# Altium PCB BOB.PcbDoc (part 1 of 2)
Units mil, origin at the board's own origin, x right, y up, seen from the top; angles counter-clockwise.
Board outline 7000 x 12000 mil, 6 copper layers (Top Layer, Int1 (GND), Int2 (Sign), Int3 (Sign), Int4 (GND2), Bottom Layer), stack 63.868 mil thick; 173 components, 165 nets, 617 pads, 174 vias.
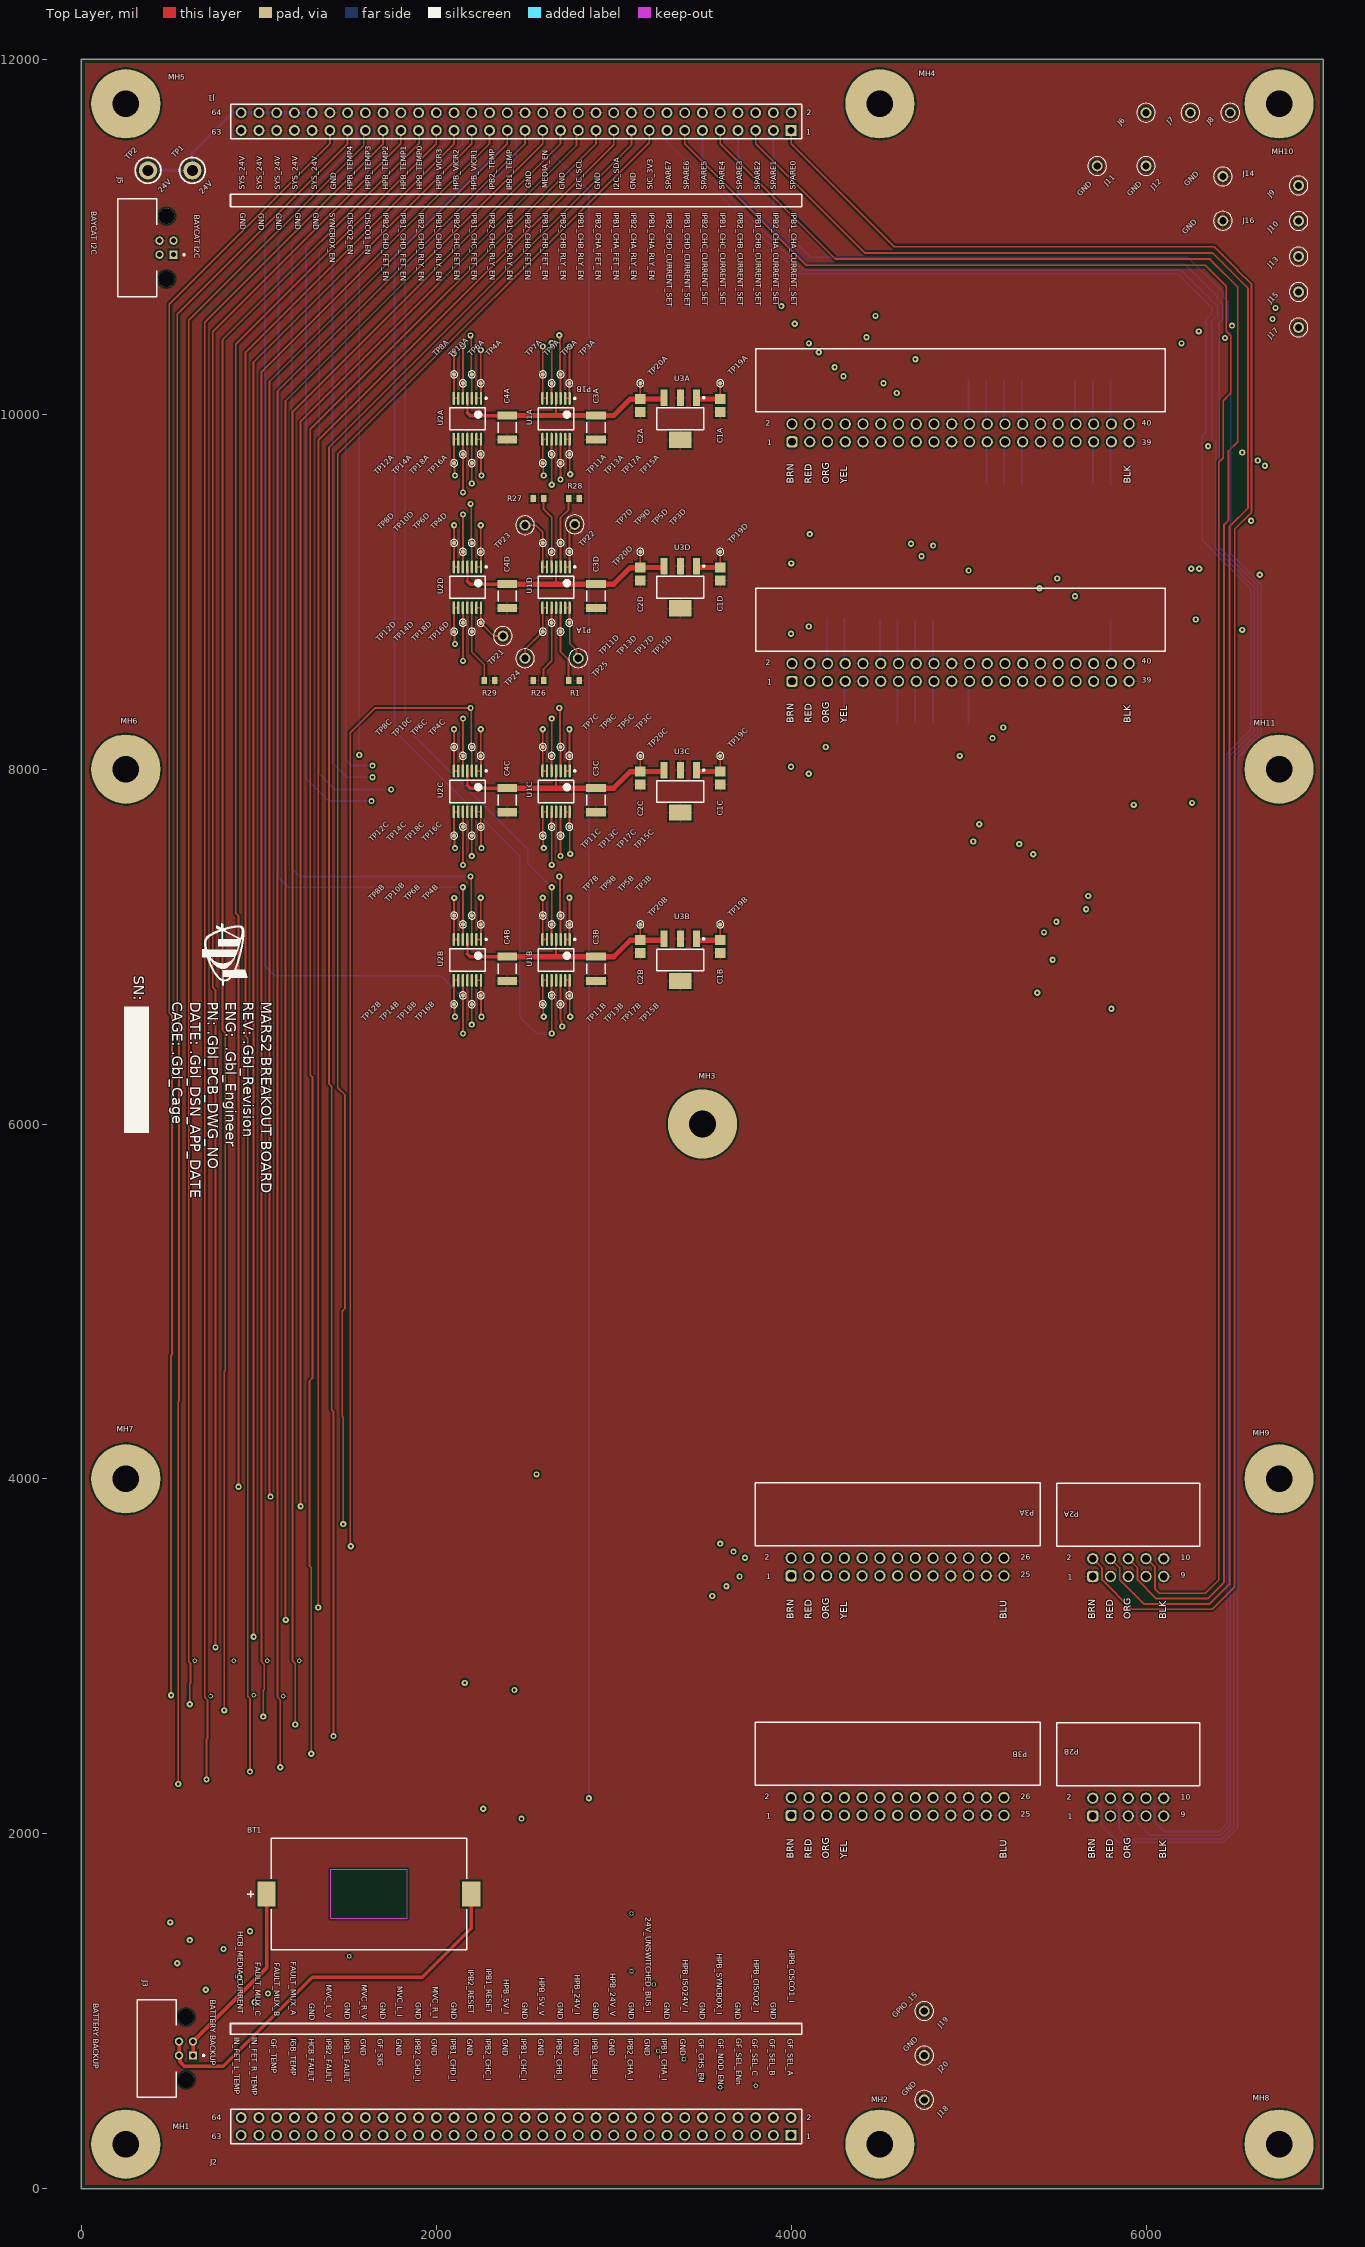
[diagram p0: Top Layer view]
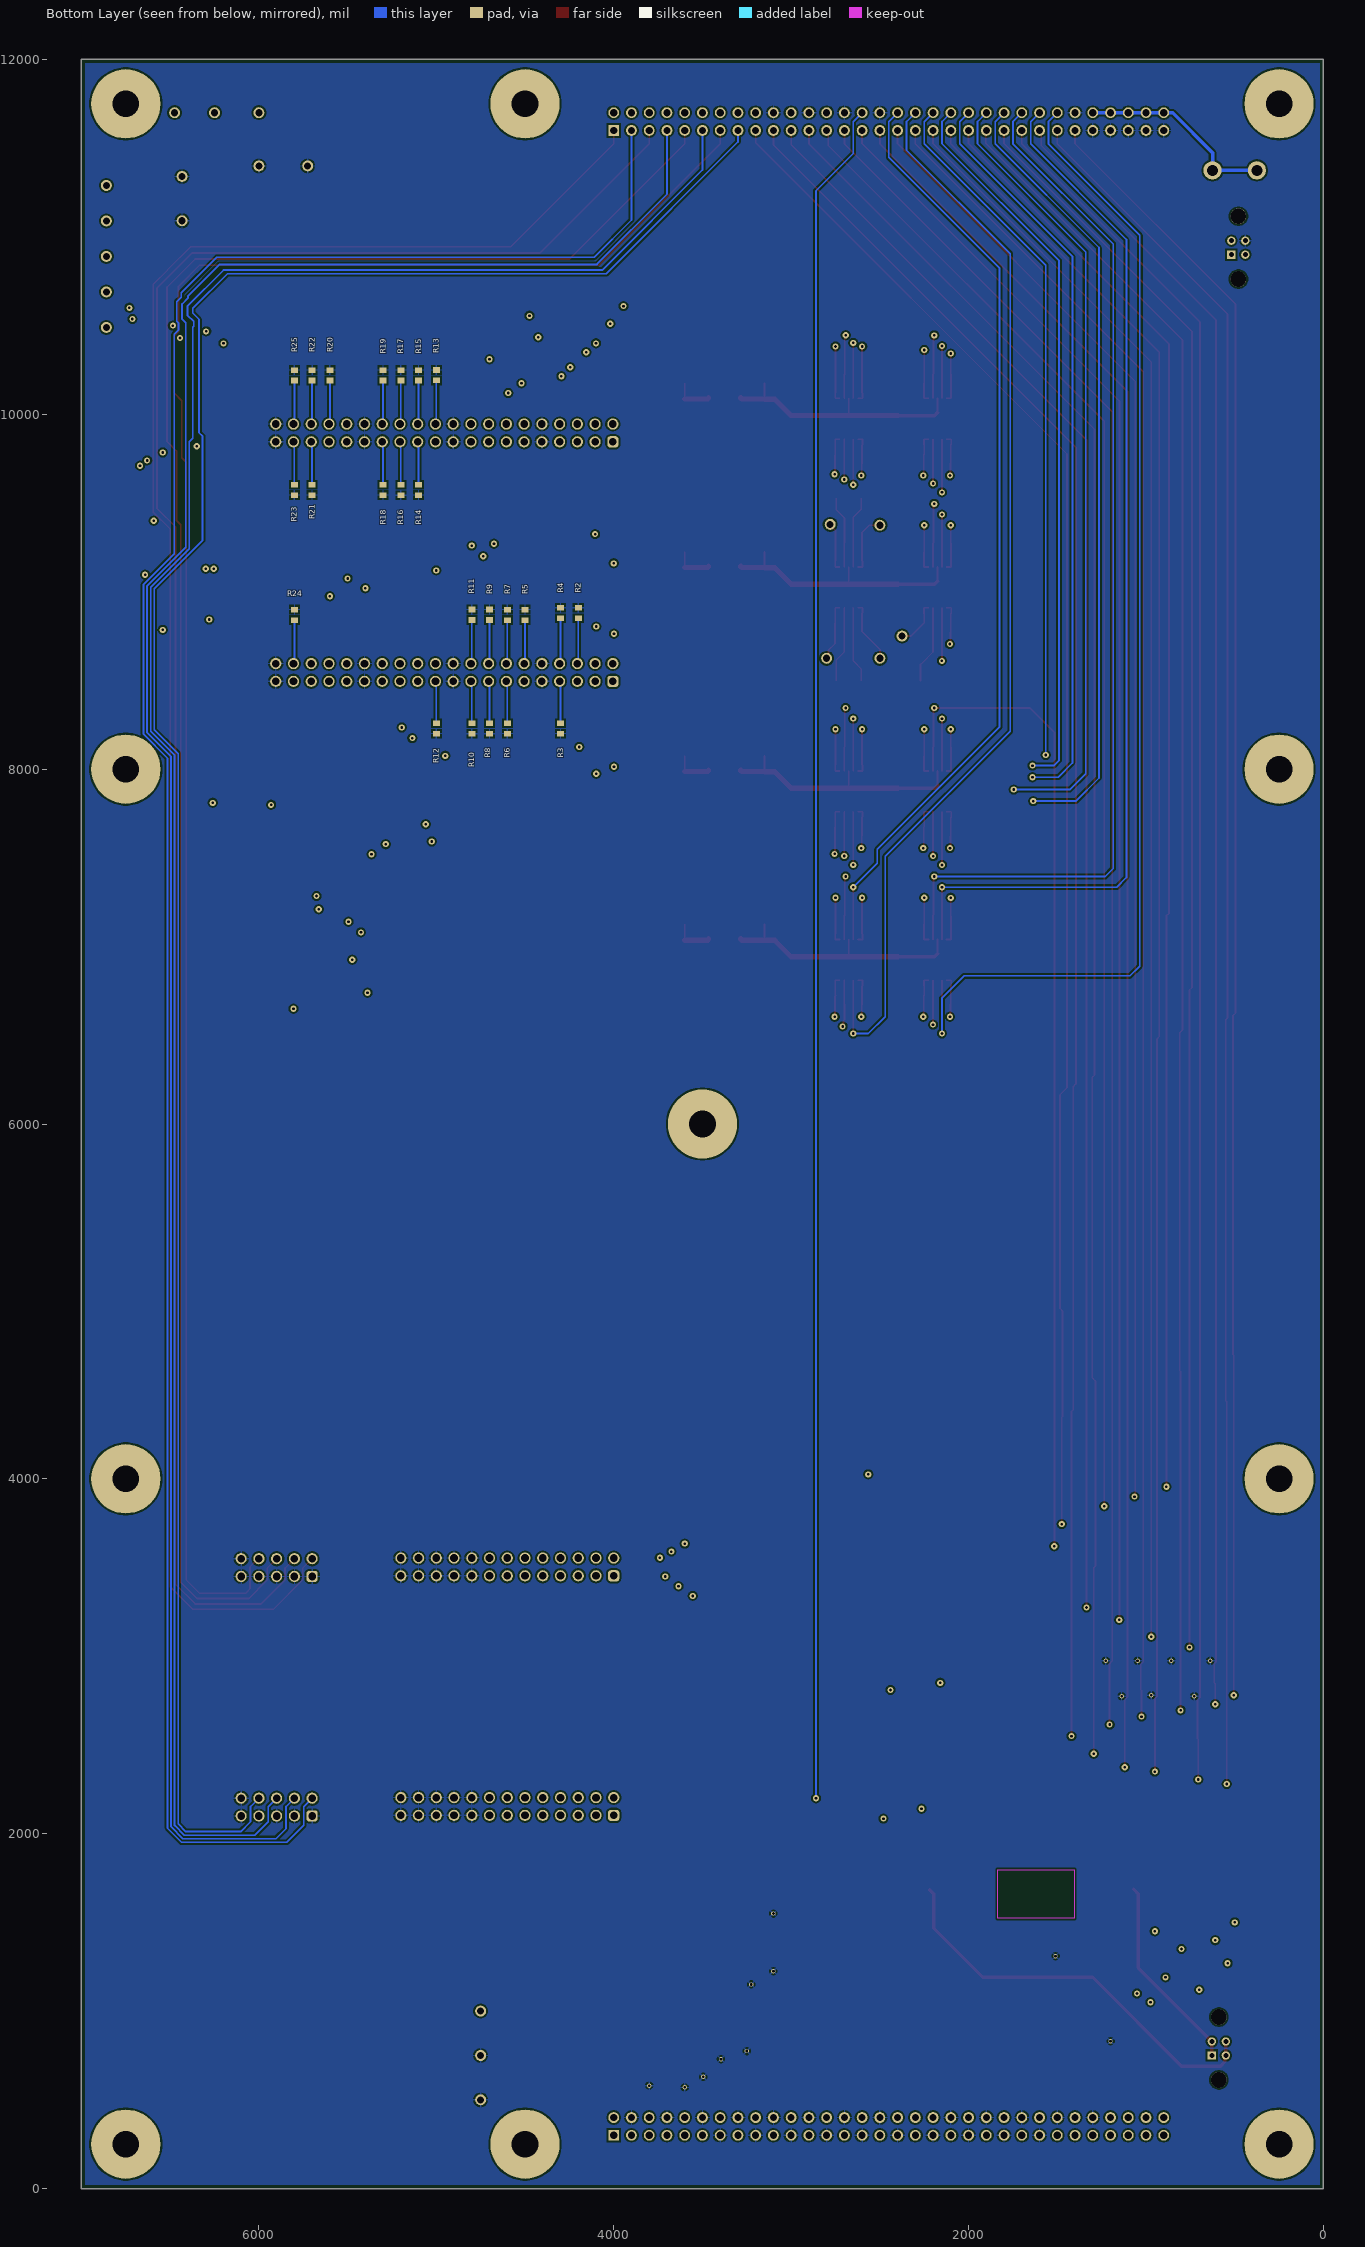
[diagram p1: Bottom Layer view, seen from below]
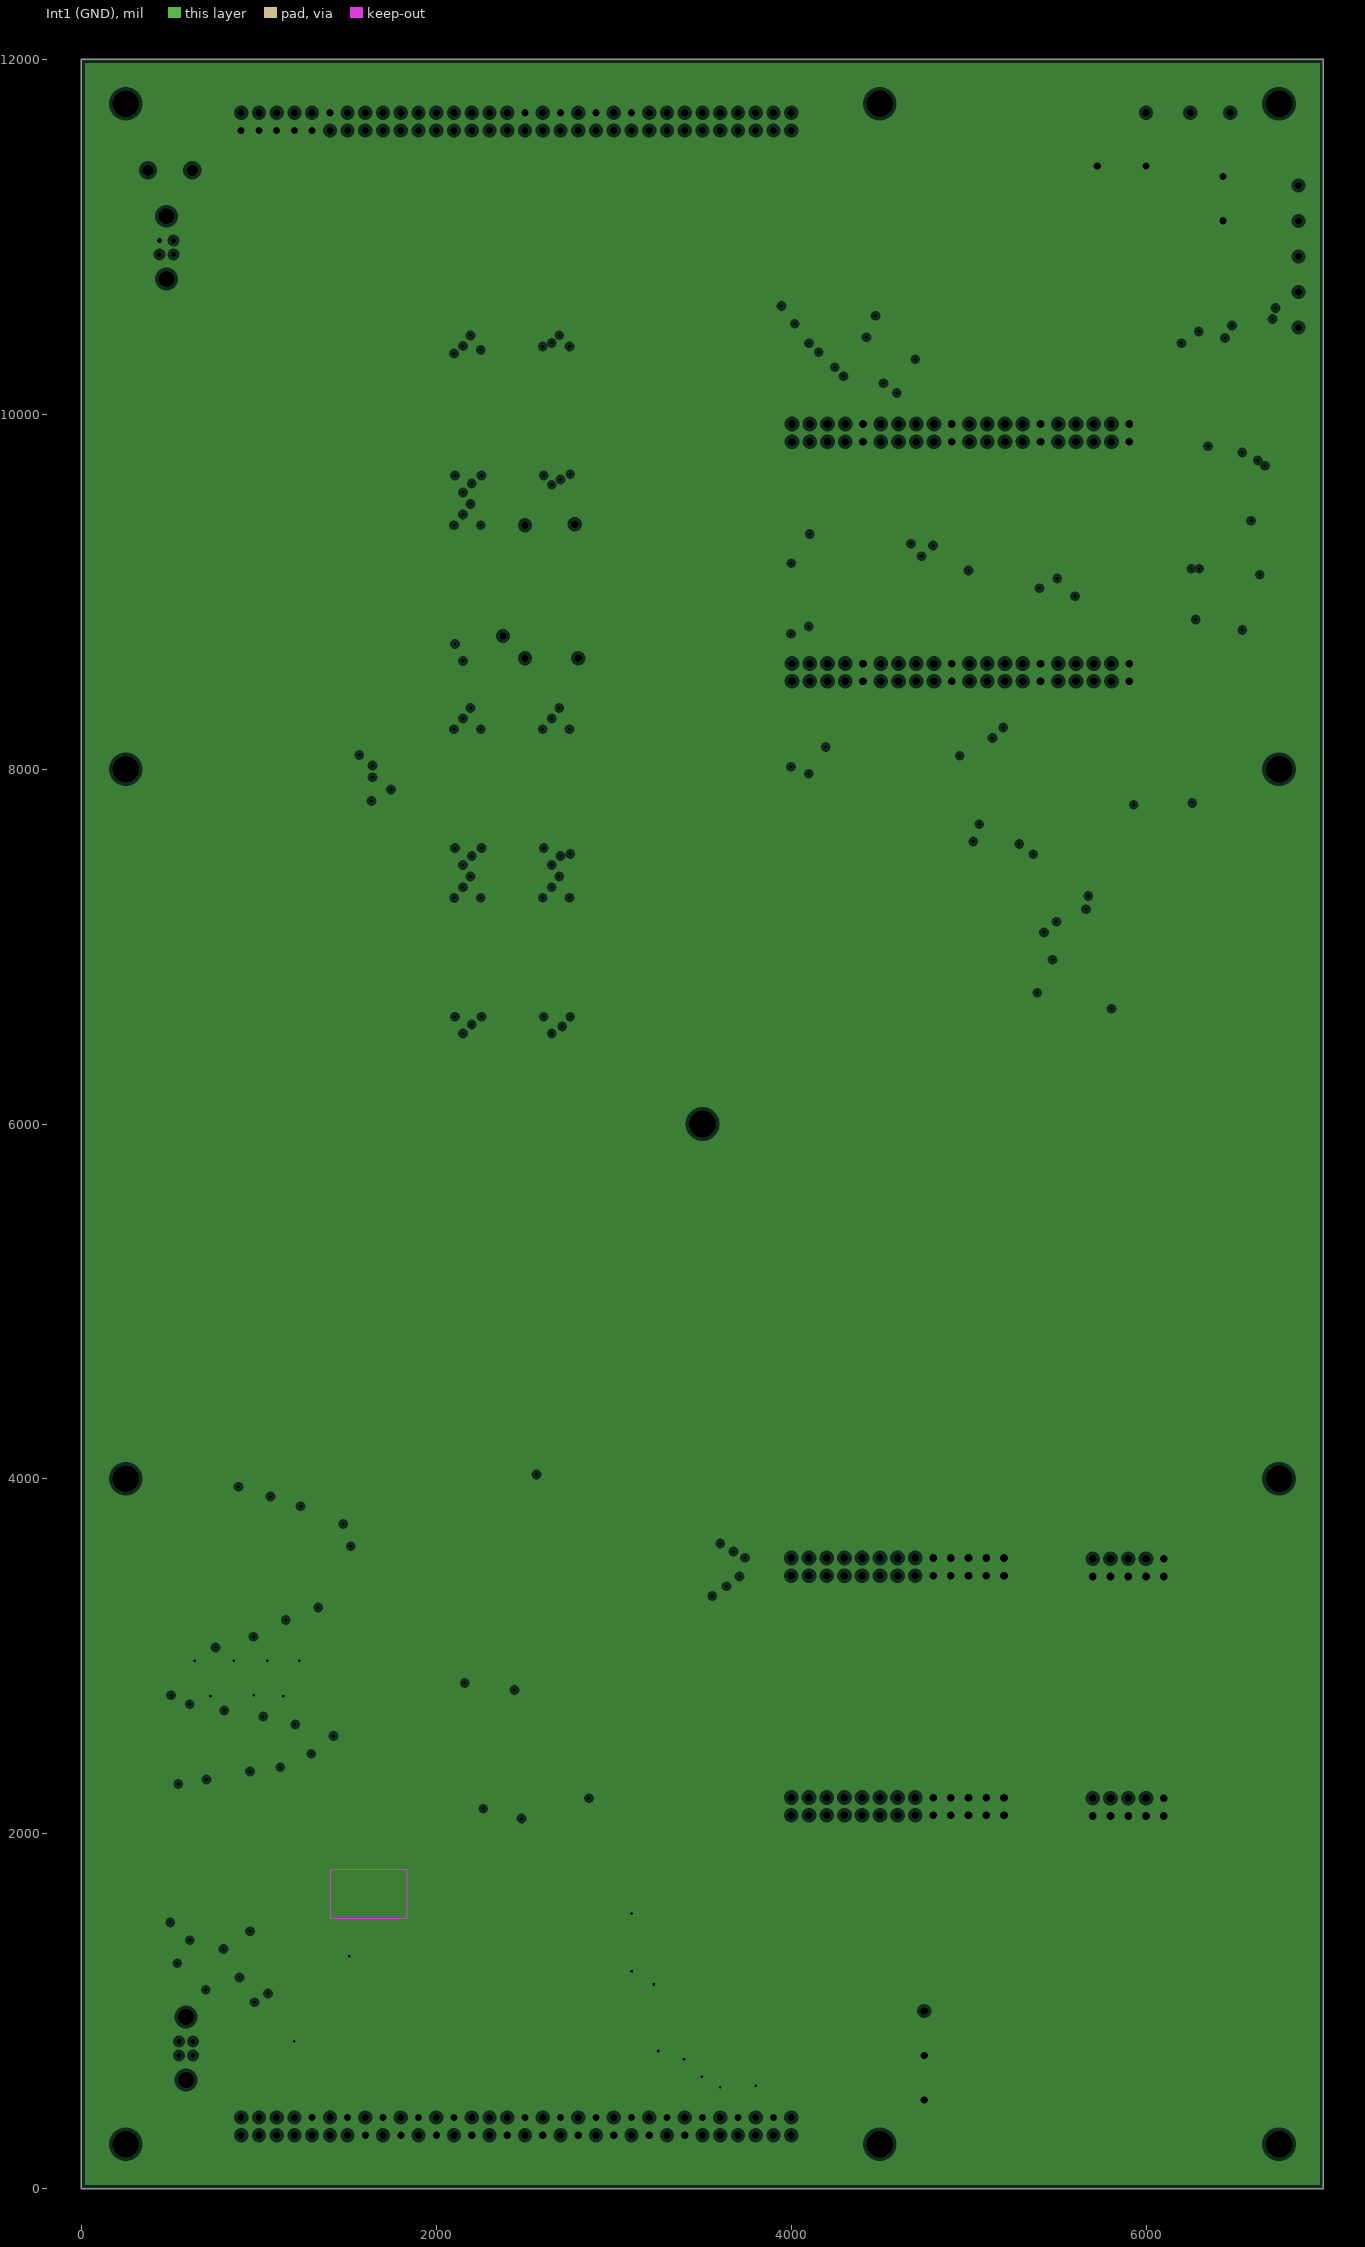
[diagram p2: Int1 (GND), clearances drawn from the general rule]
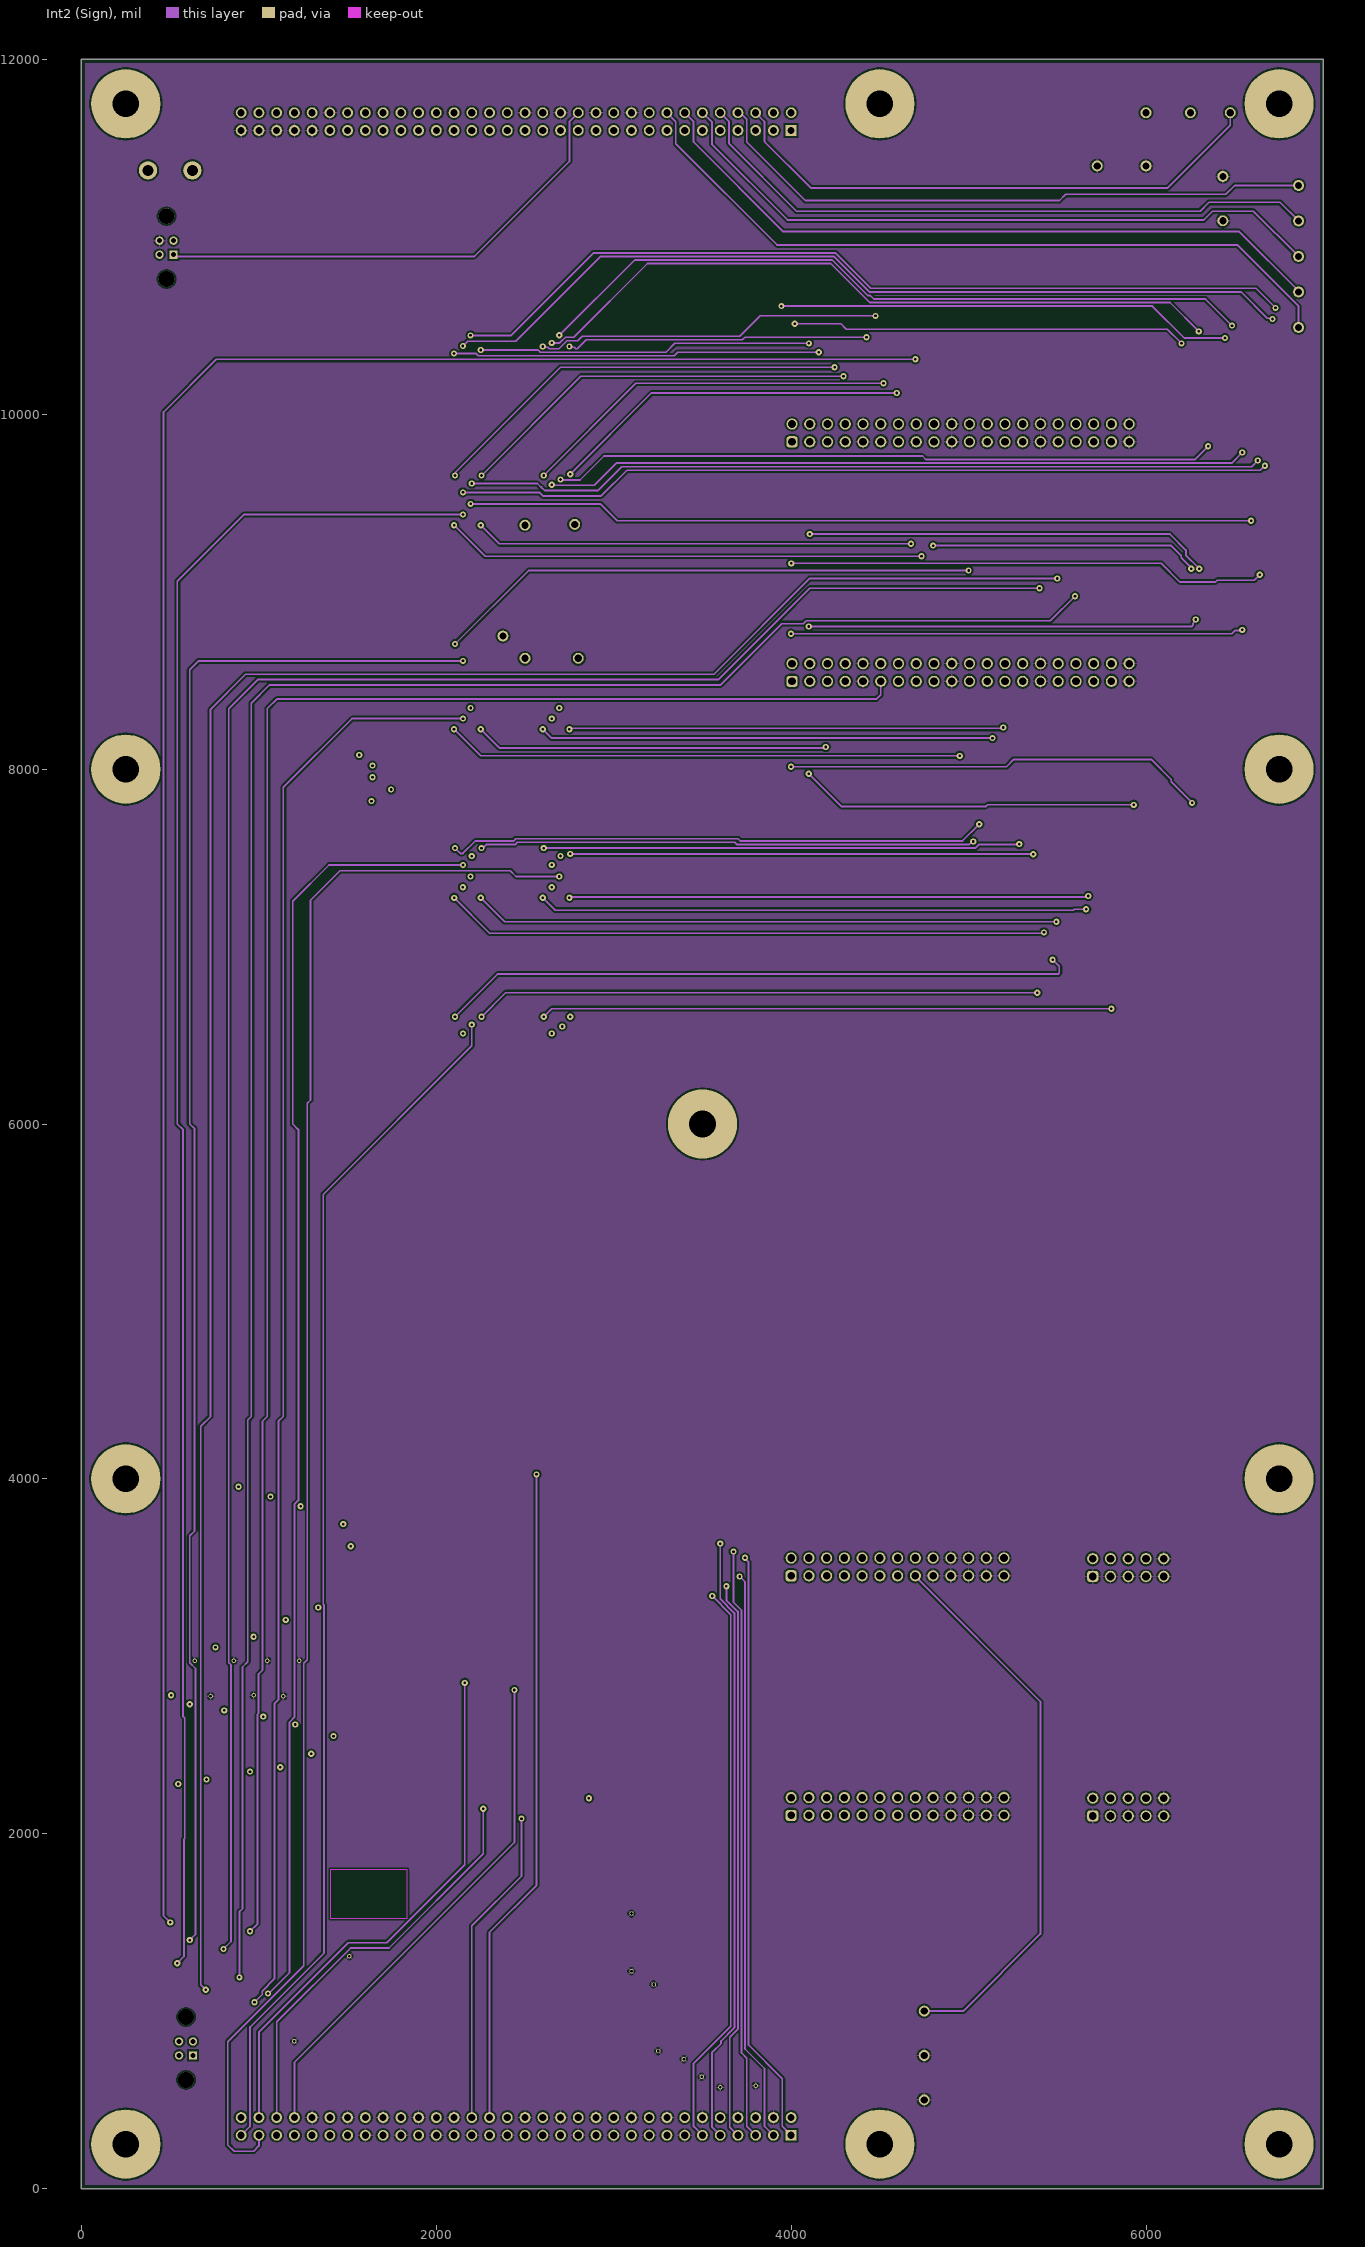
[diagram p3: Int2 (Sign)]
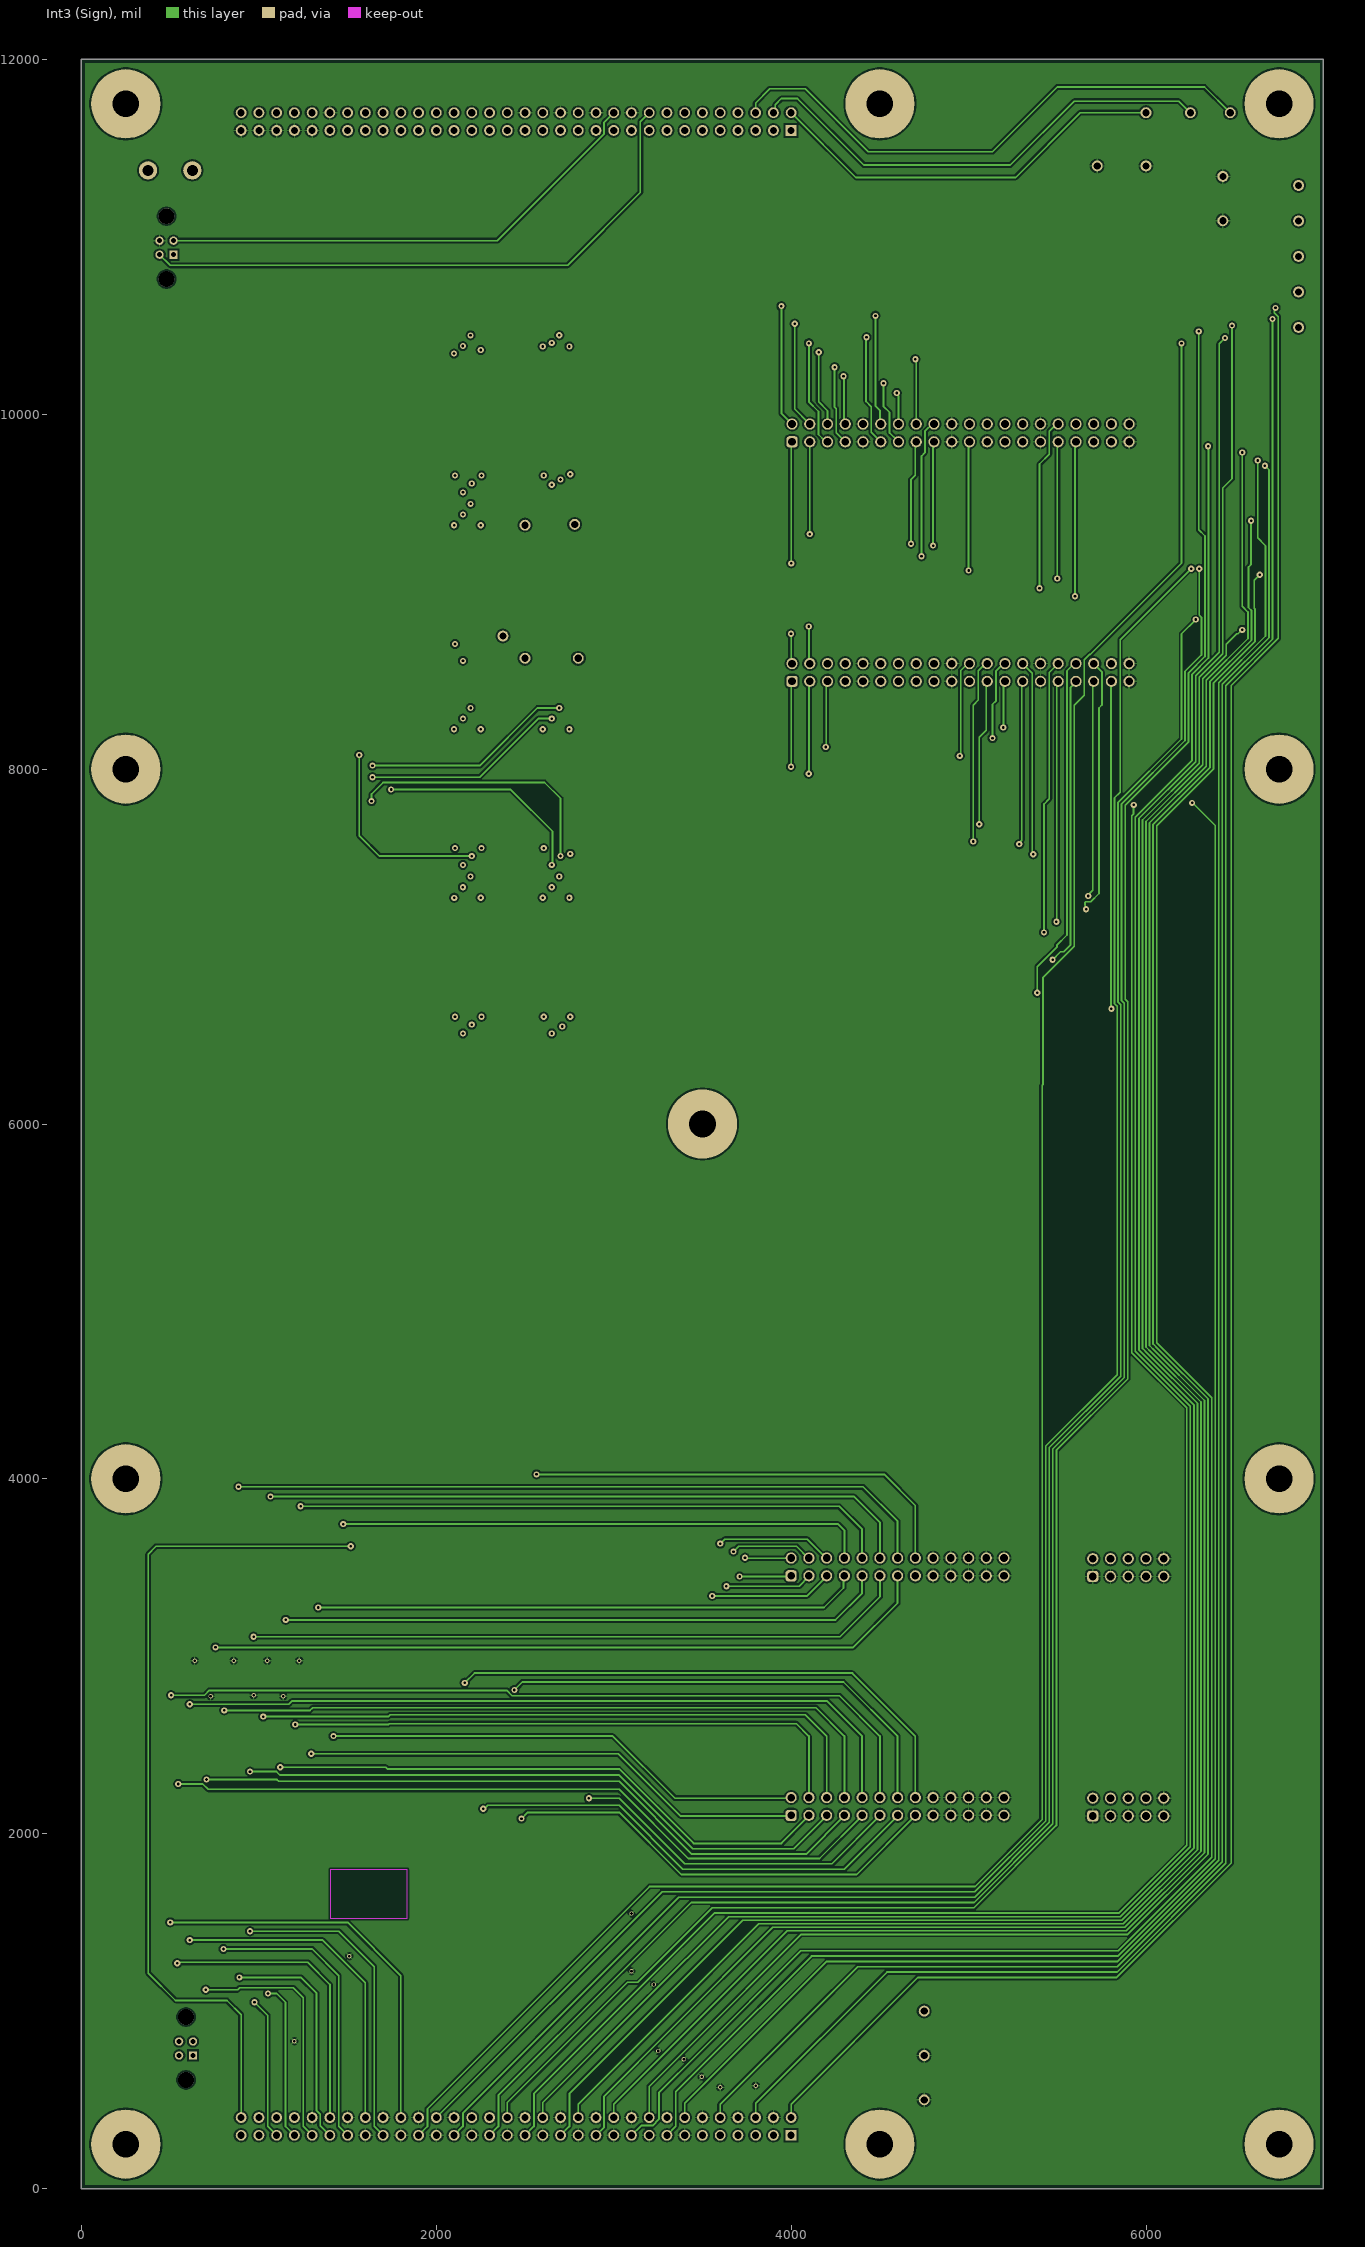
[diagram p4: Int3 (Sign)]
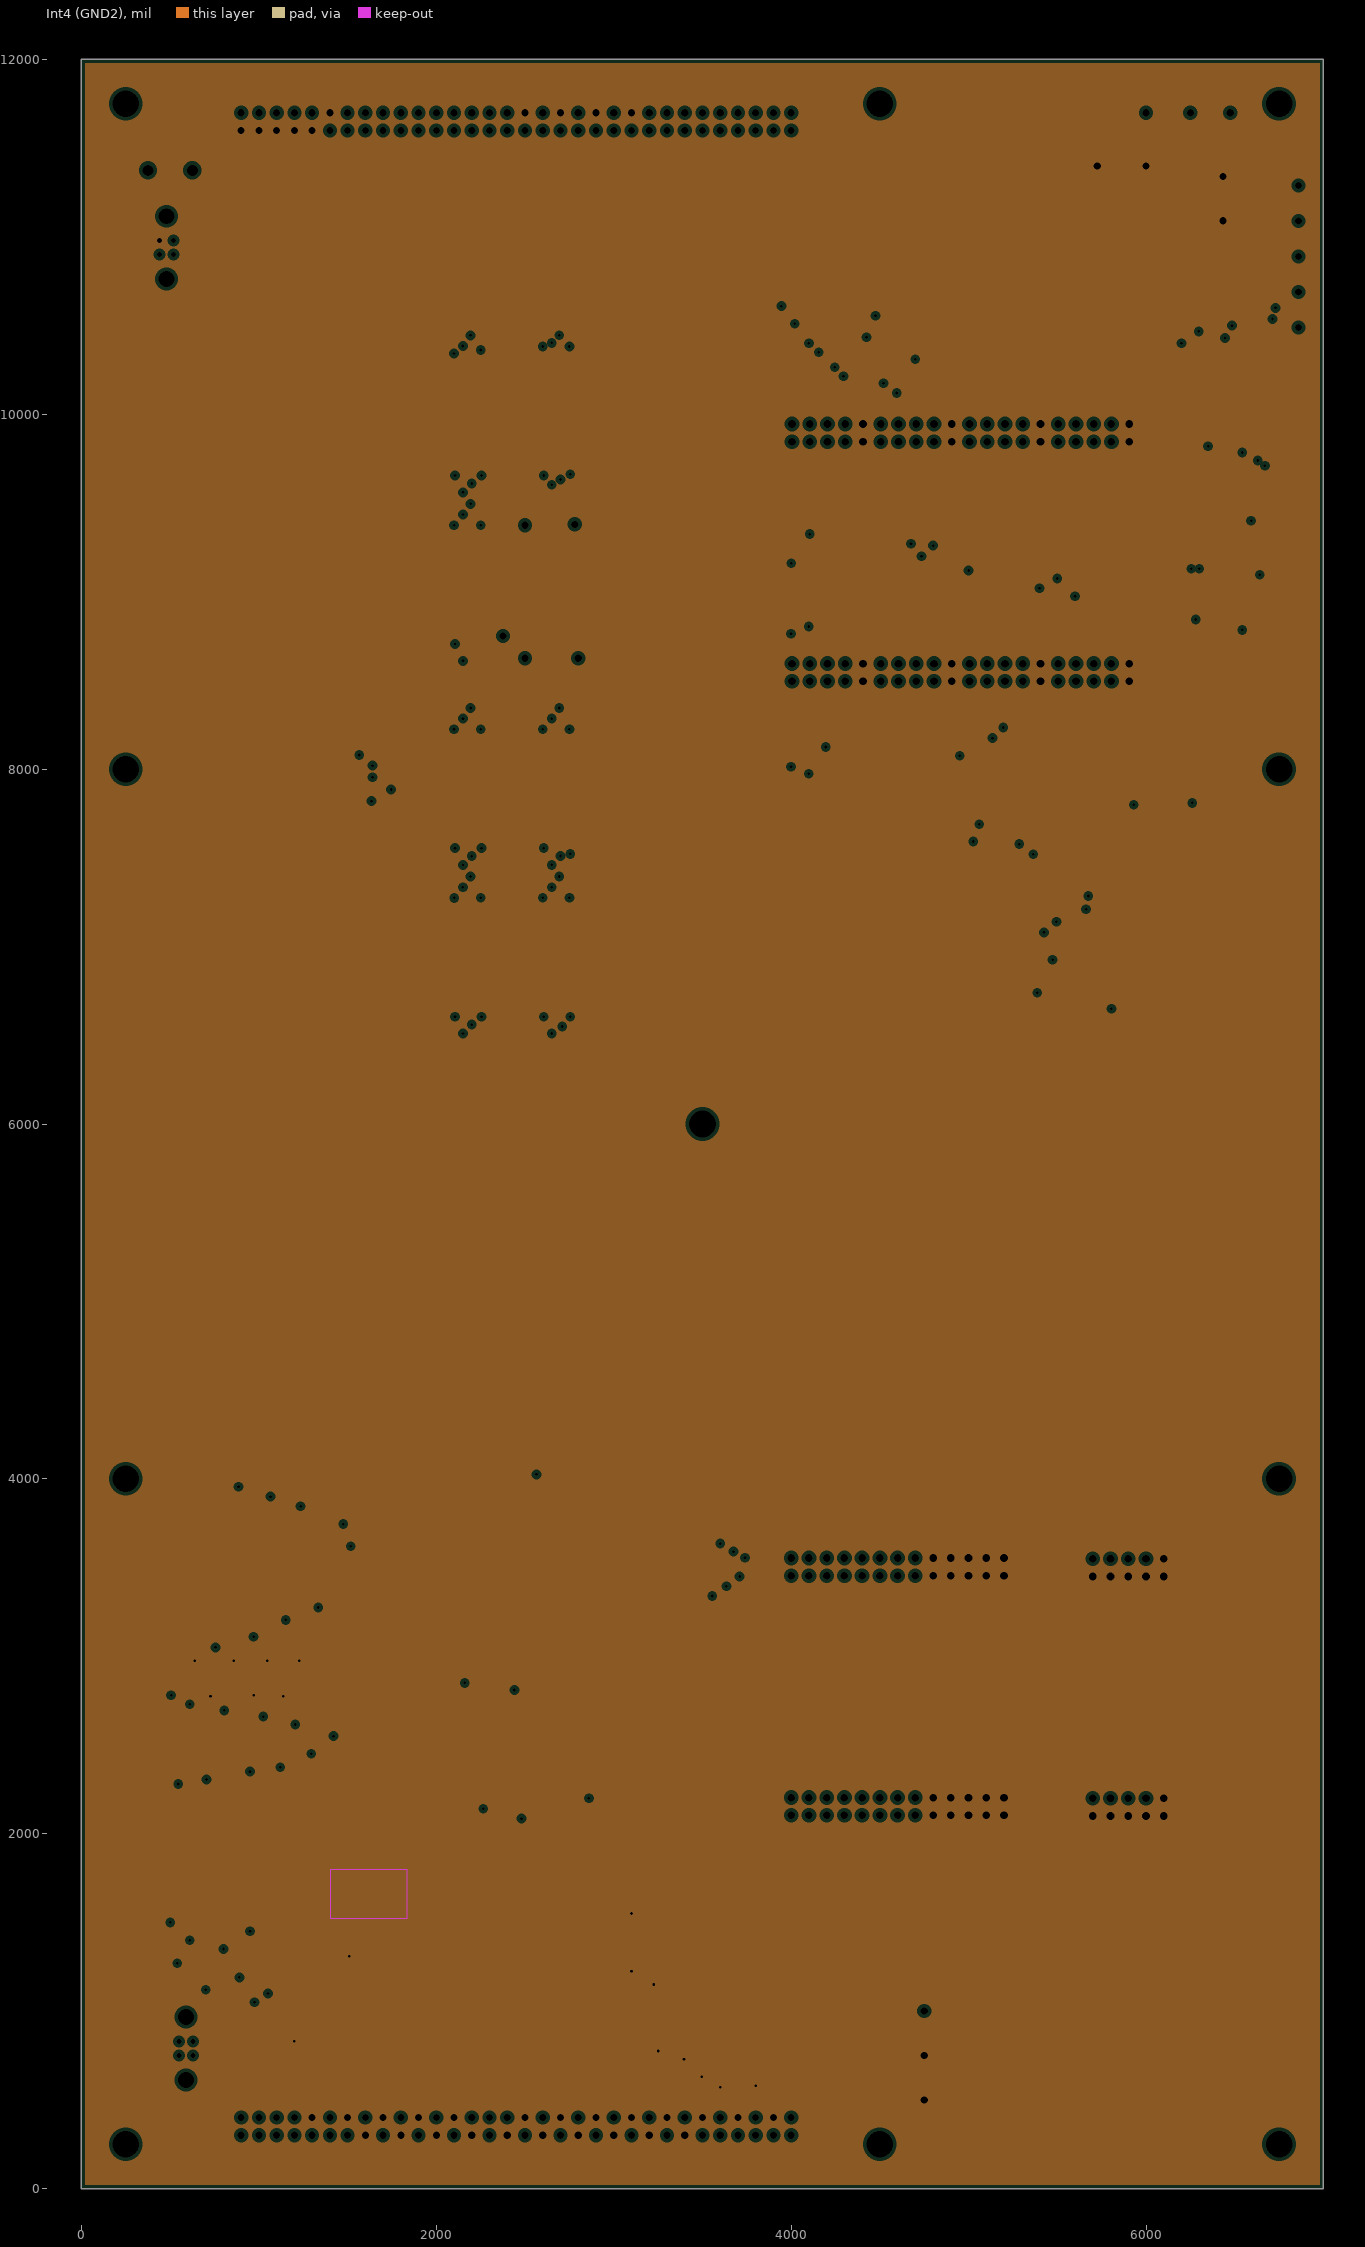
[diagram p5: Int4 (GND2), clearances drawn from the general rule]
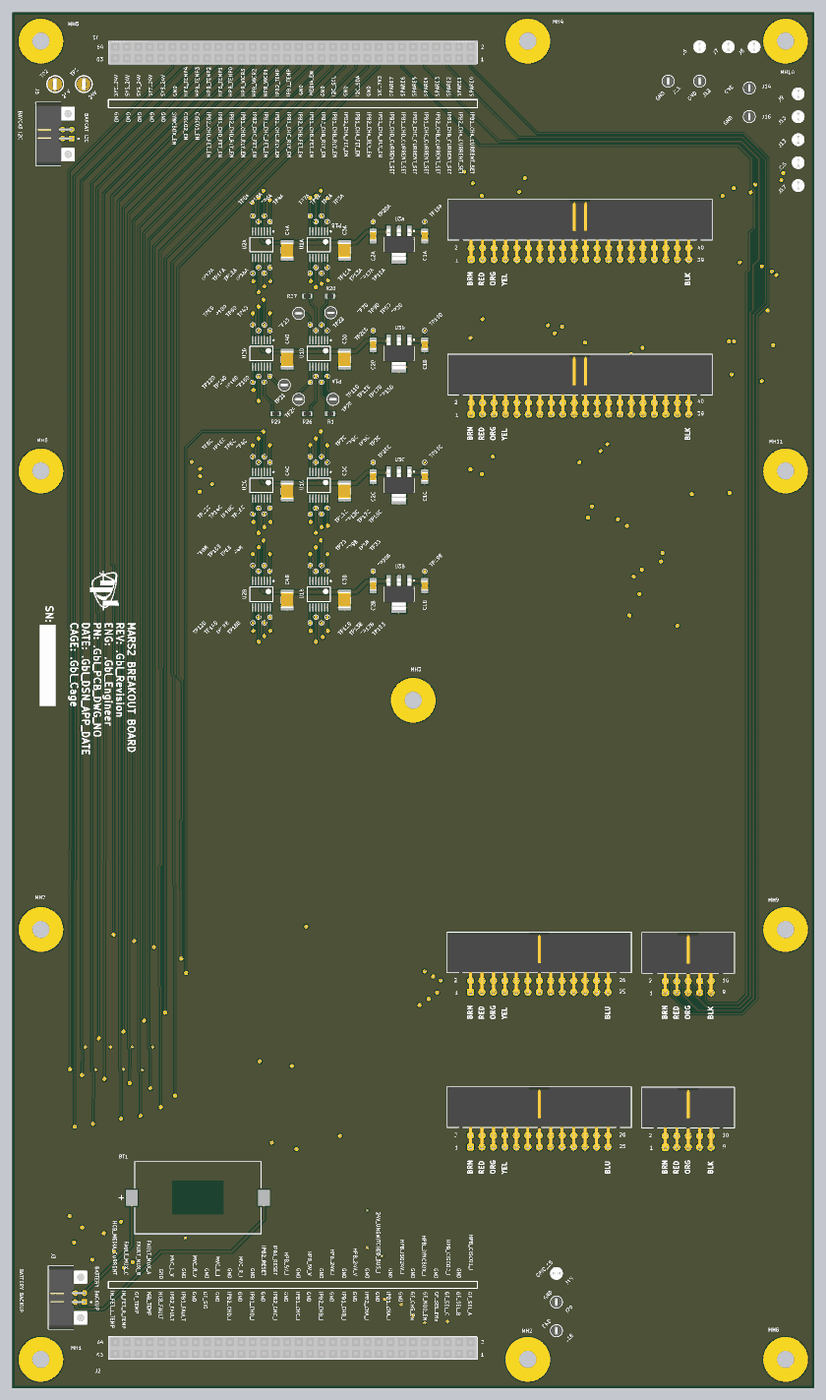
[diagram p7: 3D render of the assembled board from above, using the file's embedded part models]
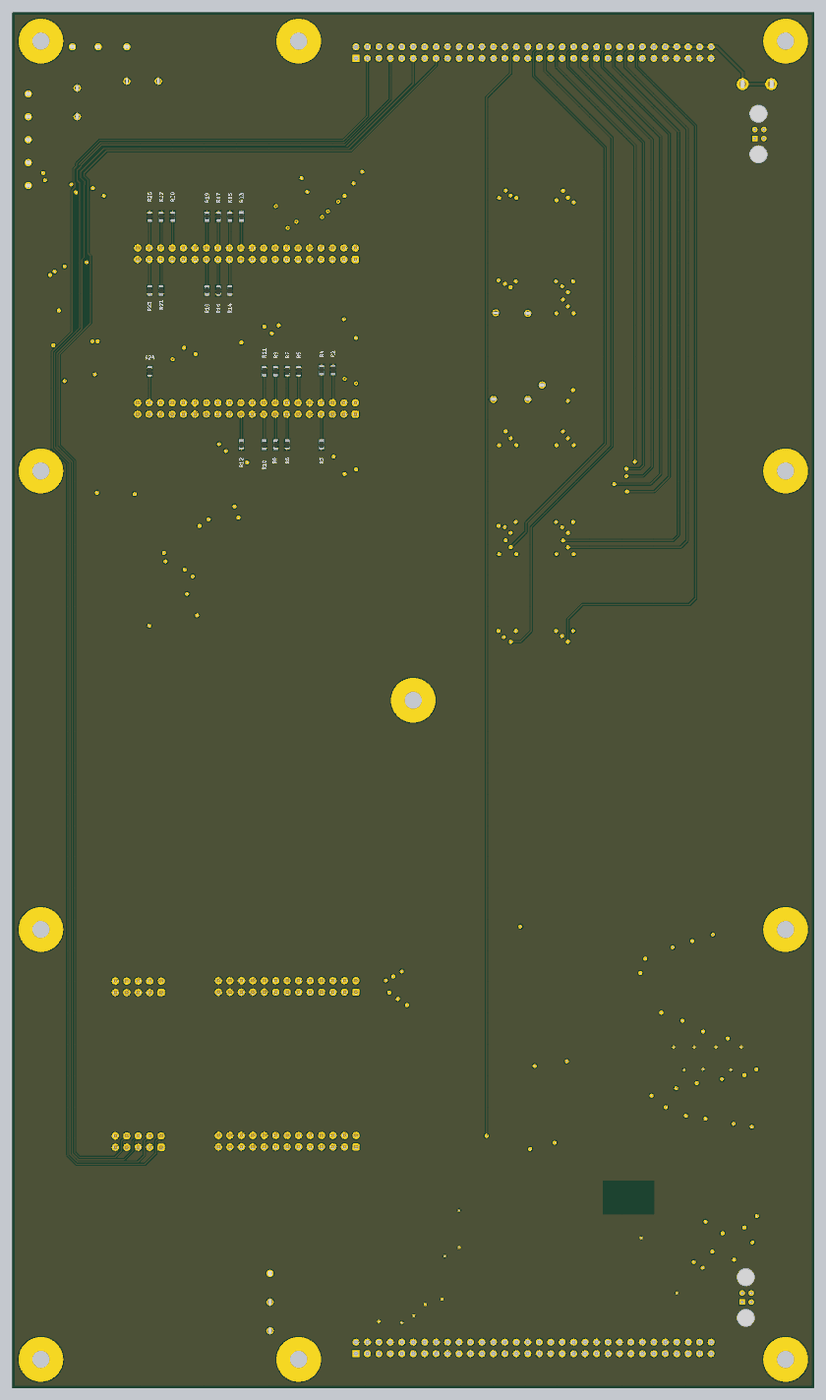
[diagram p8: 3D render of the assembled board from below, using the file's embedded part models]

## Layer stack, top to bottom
Top Solder: solder mask 1, SM-001, Dk 4
Top Layer: signal copper 1.378
Dielectric 1: prepreg 4.6, PP-016, Dk 4.4
Dielectric 2: prepreg 4.6, PP-016, Dk 4.4
Int1 (GND): plane copper 1.378, net GND
Dielectric 3: core 14, Core-035, Dk 4.7
Int2 (Sign): signal copper 1.378
Dielectric 4: prepreg 4.6, PP-016, Dk 4.4
Dielectric 5: prepreg 4.6, PP-016, Dk 4.4
Int3 (Sign): signal copper 1.378
Dielectric 6: core 14, Core-035, Dk 4.7
Int4 (GND2): plane copper 1.378, net GND
Dielectric 7: prepreg 4.6, PP-016, Dk 4.4
Dielectric 8: prepreg 4.6, PP-016, Dk 4.4
Bottom Layer: signal copper 1.378
Bottom Solder: solder mask 1, SM-001, Dk 4

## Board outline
0,0 0,12000 7000,12000 7000,0

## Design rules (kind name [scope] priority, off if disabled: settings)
BoardOutlineClearance [All] p1: gap=20 ignorepadtopadclearanceinfootprint=FALSE
Clearance Clearance_Traces [All] p1: gap=10 ignorepadtopadclearanceinfootprint=FALSE except(0: Arc-Hole Track-Hole SMDPad-Hole THPad-Hole Via-Hole Fill-Hole Poly-Hole Region-Hole Text-Hole)
Clearance Clearance_1 [All] p2: gap=10 ignorepadtopadclearanceinfootprint=FALSE except(0: Arc-Hole Track-Hole SMDPad-Hole THPad-Hole Via-Hole Fill-Hole Poly-Hole Region-Hole Text-Hole)
HoleSize [All] p1: absolutevalues=TRUE maxlimit=700 minlimit=1 maxpercent=80.000 minpercent=20.000
MinimumSolderMaskSliver [All] p1: minsoldermaskwidth=4
NetAntennae [All] p1: netantennaetolerance=250
PlaneClearance [All] p1: clearance=20
PlaneConnect [All] p1: planeconnectstyle=Relief reliefexpansion=20 reliefentries=4 reliefconductorwidth=10 reliefairgap=10
PolygonConnect [All] p1: connectstyle=Relief reliefconductorwidth=10 reliefentries=4 polygonreliefangle="90 Angle" airgapwidth=10
RoomDefinition "Voltage Buffer - 4CH Bank 3" [InComponentClass('Voltage Buffer - 4CH Bank 3')] p1: confinementstyle=ConfineIn formatcopy=TRUE lockcomponents=FALSE outline 3675,8175 2025,8175 2025,7575 3675,7575
RoomDefinition "Voltage Buffer - 4CH Bank 2" [InComponentClass('Voltage Buffer - 4CH Bank 2')] p2: confinementstyle=ConfineIn formatcopy=TRUE lockcomponents=FALSE outline 3675,7225 2025,7225 2025,6625 3675,6625
RoomDefinition "Voltage Buffer - 4CH Bank 4" [InComponentClass('Voltage Buffer - 4CH Bank 4')] p3: confinementstyle=ConfineIn formatcopy=TRUE lockcomponents=FALSE outline 3675,9325 2025,9325 2025,8725 3675,8725
RoomDefinition "Voltage Buffer - 4CH Bank 1" [InComponentClass('Voltage Buffer - 4CH Bank 1')] p4: confinementstyle=ConfineIn formatcopy=TRUE lockcomponents=FALSE outline 3675,10275 2025,10275 2025,9675 3675,9675
RoutingVias [All] p1: holewidth=28 width=50 viastyle="Through Hole" minholewidth=28 minwidth=50 maxholewidth=28 maxwidth=50
SilkToSilkClearance [All] p1: silktosilkclearance=3
SilkToSolderMaskClearance [IsPad] p1: minsilkscreentomaskgap=3 clearancetoexposedcopper=TRUE
SolderMaskExpansion [All] p1: expansion=2 istentingtop=FALSE
Width [All] p1: maxlimit=50 minlimit=10 preferedwidth=10 minimp=50.000000 maximp=50.000000 favimp=50.000000
23 further rules are at their usual default settings.

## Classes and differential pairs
channel class 8CH-Voltage-Buffer: "Voltage Buffer - 4CH Bank 1" "Voltage Buffer - 4CH Bank 2" "Voltage Buffer - 4CH Bank 3" "Voltage Buffer - 4CH Bank 4"
component class "Voltage Buffer - 4CH Bank 4": C1D C2D C3D C4D TP3D TP4D TP5D TP6D TP7D TP8D TP9D TP10D TP11D TP12D TP13D TP14D TP15D TP16D TP17D TP18D TP19D TP20D U1D U2D U3D
component class "Voltage Buffer - 4CH Bank 3": C1C C2C C3C C4C TP3C TP4C TP5C TP6C TP7C TP8C TP9C TP10C TP11C TP12C TP13C TP14C TP15C TP16C TP17C TP18C TP19C TP20C U1C U2C U3C
component class "Voltage Buffer - 4CH Bank 2": C1B C2B C3B C4B TP3B TP4B TP5B TP6B TP7B TP8B TP9B TP10B TP11B TP12B TP13B TP14B TP15B TP16B TP17B TP18B TP19B TP20B U1B U2B U3B
component class "Voltage Buffer - 4CH Bank 1": C1A C2A C3A C4A TP3A TP4A TP5A TP6A TP7A TP8A TP9A TP10A TP11A TP12A TP13A TP14A TP15A TP16A TP17A TP18A TP19A TP20A U1A U2A U3A
channel class "CTI Breakout": CTI_1 CTI_2
component class "Test Points": J6 J7 J8 J9 J10 J11 J12 J13 J14 J15 J16 J17 J18 J19 J20 TP1 TP2
component class Mezz: J1 J2
component class CTI_2: P1B P2B P3B
component class CTI_1: P1A P2A P3A
component class Coversheet: MH1 MH2 MH3 MH4 MH5 MH6 MH7 MH8 MH9 MH10 MH11 R1 R2 R3 R4 R5 R6 R7 R8 R9 R10 R11 R12 R13 R14 R15 R16 R17 R18 R19 R20 R21 R22 R23 R24 R25 R26 R27 R28 R29 TP21 TP22 TP23 TP24 TP25
component class BAYCAT: BT1 J3 J5

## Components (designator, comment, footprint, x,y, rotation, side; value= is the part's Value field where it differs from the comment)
BT1 "BA2032SM" MPD-BA2032SM_V 1620,1660 r0 top
C1A "Capacitor 2.2uF 10%, 50V, X7R, 0805" CAPC2013X95X50ML10T25 3600,10050 r90 top value=2.2uF (schematic designator C1)
C1B "Capacitor 2.2uF 10%, 50V, X7R, 0805" CAPC2013X95X50ML10T25 3600,7000 r90 top value=2.2uF (schematic designator C1)
C1C "Capacitor 2.2uF 10%, 50V, X7R, 0805" CAPC2013X95X50ML10T25 3600,7950 r90 top value=2.2uF (schematic designator C1)
C1D "Capacitor 2.2uF 10%, 50V, X7R, 0805" CAPC2013X95X50ML10T25 3600,9100 r90 top value=2.2uF (schematic designator C1)
C2A "Capacitor 2.2uF 10%, 50V, X7R, 0805" CAPC2013X95X50ML10T25 3150,10050 r90 top value=2.2uF (schematic designator C2)
C2B "Capacitor 2.2uF 10%, 50V, X7R, 0805" CAPC2013X95X50ML10T25 3150,7000 r90 top value=2.2uF (schematic designator C2)
C2C "Capacitor 2.2uF 10%, 50V, X7R, 0805" CAPC2013X95X50ML10T25 3150,7950 r90 top value=2.2uF (schematic designator C2)
C2D "Capacitor 2.2uF 10%, 50V, X7R, 0805" CAPC2013X95X50ML10T25 3150,9100 r90 top value=2.2uF (schematic designator C2)
C3A "Capacitor 1uF 10%, 50V, X7R, 1210" CAPC3225X270X30ML30 2900,9925 r270 top value=1uF (schematic designator C3)
C3B "Capacitor 1uF 10%, 50V, X7R, 1210" CAPC3225X270X30ML30 2900,6875 r270 top value=1uF (schematic designator C3)
C3C "Capacitor 1uF 10%, 50V, X7R, 1210" CAPC3225X270X30ML30 2900,7825 r270 top value=1uF (schematic designator C3)
C3D "Capacitor 1uF 10%, 50V, X7R, 1210" CAPC3225X270X30ML30 2900,8975 r270 top value=1uF (schematic designator C3)
C4A "Capacitor 1uF 10%, 50V, X7R, 1210" CAPC3225X270X30ML30 2400,9925 r270 top value=1uF (schematic designator C4)
C4B "Capacitor 1uF 10%, 50V, X7R, 1210" CAPC3225X270X30ML30 2400,6875 r270 top value=1uF (schematic designator C4)
C4C "Capacitor 1uF 10%, 50V, X7R, 1210" CAPC3225X270X30ML30 2400,7825 r270 top value=1uF (schematic designator C4)
C4D "Capacitor 1uF 10%, 50V, X7R, 1210" CAPC3225X270X30ML30 2400,8975 r270 top value=1uF (schematic designator C4)
J1 "ESQ-132-14-G-D" SMTC-ESQ-132-14-X-D 4000,11600 r180 top
J2 "ESQ-132-14-G-D" SMTC-ESQ-132-14-X-D 4000,300 r180 top
J3 "M80-5400442" M80-5400442-Footprint-1 589.37,789.37 r270 top
J5 "M80-5400442" M80-5400442-Footprint-1 479.37,10939.37 r270 top
J6 "5002" FP-5002-MFG 6000,11700 r90 top
J7 "5002" FP-5002-MFG 6250,11700 r90 top
J8 "5002" FP-5002-MFG 6475,11700 r90 top
J9 "5002" FP-5002-MFG 6860,11290 r90 top
J10 "5002" FP-5002-MFG 6860,11090 r90 top
J11 "5001" FP-5001-MFG 5725,11400 r90 top
J12 "5001" FP-5001-MFG 6000,11400 r90 top
J13 "5002" FP-5002-MFG 6860,10890 r90 top
J14 "5001" FP-5001-MFG 6433,11341 r90 top
J15 "5002" FP-5002-MFG 6860,10690 r90 top
J16 "5001" FP-5001-MFG 6433,11091 r90 top
J17 "5002" FP-5002-MFG 6860,10490 r90 top
J18 "5001" FP-5001-MFG 4750,500 r90 top
J19 "5002" FP-5002-MFG 4750,1000 r0 top
J20 "5001" FP-5001-MFG 4750,750 r90 top
MH1 "MH-MARS2-6-32" "MH-M3-Footprint-1 - Oversized MARS2" 250,250 r0 top
MH2 "MH-MARS2-6-32" "MH-M3-Footprint-1 - Oversized MARS2" 4500,250 r0 top
MH3 "MH-MARS2-6-32" "MH-M3-Footprint-1 - Oversized MARS2" 3500,6000 r0 top
MH4 "MH-MARS2-6-32" "MH-M3-Footprint-1 - Oversized MARS2" 4500,11750 r0 top
MH5 "MH-MARS2-6-32" "MH-M3-Footprint-1 - Oversized MARS2" 250,11750 r0 top
MH6 "MH-MARS2-6-32" "MH-M3-Footprint-1 - Oversized MARS2" 250,8000 r0 top
MH7 "MH-MARS2-6-32" "MH-M3-Footprint-1 - Oversized MARS2" 250,4000 r0 top
MH8 "MH-MARS2-6-32" "MH-M3-Footprint-1 - Oversized MARS2" 6750,250 r0 top
MH9 "MH-MARS2-6-32" "MH-M3-Footprint-1 - Oversized MARS2" 6750,4000 r0 top
MH10 "MH-MARS2-6-32" "MH-M3-Footprint-1 - Oversized MARS2" 6750,11750 r0 top
MH11 "MH-MARS2-6-32" "MH-M3-Footprint-1 - Oversized MARS2" 6750,8000 r0 top
P1A "61204021721" 61204021721 4955,8841.65 r180 top (schematic designator P1)
P1B "61204021721" 61204021721 4955,10191.65 r180 top (schematic designator P1)
P2A "61202621721" 61202621721 4600,3800 r180 top (schematic designator P2)
P2B "61202621721" 61202621721 4600,2450 r180 top (schematic designator P2)
P3A "61201021721" 61201021721 5900,3796.65 r180 top (schematic designator P3)
P3B "61201021721" 61201021721 5900,2446.65 r180 top (schematic designator P3)
R1 "Resistor 10k +/-1% 0603 100 mW" RESC1608X55X25ML10T15 2775,8500 r180 top value=10k
R2 "Resistor 10k +/-1% 0603 100 mW" RESC1608X55X25ML10T15 4200,8880 r90 bottom value=10k
R3 "Resistor 10k +/-1% 0603 100 mW" RESC1608X55X25ML10T15 4300,8230 r270 bottom value=10k
R4 "Resistor 10k +/-1% 0603 100 mW" RESC1608X55X25ML10T15 4300,8880.47 r90 bottom value=10k
R5 "Resistor 10k +/-1% 0603 100 mW" RESC1608X55X25ML10T15 4500,8870 r90 bottom value=10k
R6 "Resistor 10k +/-1% 0603 100 mW" RESC1608X55X25ML10T15 4600,8230 r270 bottom value=10k
R7 "Resistor 10k +/-1% 0603 100 mW" RESC1608X55X25ML10T15 4600,8870 r90 bottom value=10k
R8 "Resistor 10k +/-1% 0603 100 mW" RESC1608X55X25ML10T15 4700,8229.53 r270 bottom value=10k
R9 "Resistor 10k +/-1% 0603 100 mW" RESC1608X55X25ML10T15 4700,8870.47 r90 bottom value=10k
R10 "Resistor 10k +/-1% 0603 100 mW" RESC1608X55X25ML10T15 4800,8229.53 r270 bottom value=10k
R11 "Resistor 10k +/-1% 0603 100 mW" RESC1608X55X25ML10T15 4800,8870.47 r90 bottom value=10k
R12 "Resistor 10k +/-1% 0603 100 mW" RESC1608X55X25ML10T15 5000,8230 r270 bottom value=10k
R13 "Resistor 10k +/-1% 0603 100 mW" RESC1608X55X25ML10T15 5000,10220.47 r270 bottom value=10k
R14 "Resistor 10k +/-1% 0603 100 mW" RESC1608X55X25ML10T15 5100.33,9574.49 r90 bottom value=10k
R15 "Resistor 10k +/-1% 0603 100 mW" RESC1608X55X25ML10T15 5100,10220 r270 bottom value=10k
R16 "Resistor 10k +/-1% 0603 100 mW" RESC1608X55X25ML10T15 5200.33,9574.02 r90 bottom value=10k
R17 "Resistor 10k +/-1% 0603 100 mW" RESC1608X55X25ML10T15 5200,10220 r270 bottom value=10k
R18 "Resistor 10k +/-1% 0603 100 mW" RESC1608X55X25ML10T15 5300.33,9574.49 r90 bottom value=10k
R19 "Resistor 10k +/-1% 0603 100 mW" RESC1608X55X25ML10T15 5300,10220 r270 bottom value=10k
R20 "Resistor 10k +/-1% 0603 100 mW" RESC1608X55X25ML10T15 5600,10220 r270 bottom value=10k
R21 "Resistor 10k +/-1% 0603 100 mW" RESC1608X55X25ML10T15 5700.33,9574.49 r90 bottom value=10k
R22 "Resistor 10k +/-1% 0603 100 mW" RESC1608X55X25ML10T15 5700,10220 r270 bottom value=10k
R23 "Resistor 10k +/-1% 0603 100 mW" RESC1608X55X25ML10T15 5800.33,9574.49 r90 bottom value=10k
R24 "Resistor 10k +/-1% 0603 100 mW" RESC1608X55X25ML10T15 5800,8870 r90 bottom value=10k
R25 "Resistor 10k +/-1% 0603 100 mW" RESC1608X55X25ML10T15 5800,10220 r270 bottom value=10k
R26 "Resistor 10k +/-1% 0603 100 mW" RESC1608X55X25ML10T15 2575,8500 r0 top value=10k
R27 "Resistor 10k +/-1% 0603 100 mW" RESC1608X55X25ML10T15 2575,9525 r0 top value=10k
R28 "Resistor 10k +/-1% 0603 100 mW" RESC1608X55X25ML10T15 2775,9525 r180 top value=10k
R29 "Resistor 10k +/-1% 0603 100 mW" RESC1608X55X25ML10T15 2300,8500 r180 top value=10k
TP1 "5005" TestPoint-5005-Footprint-1 625,11375 r90 top
TP2 "5005" TestPoint-5005-Footprint-1 375,11375 r90 top
TP3A "TPAD6R-CIRCLED" "TP06R - Circled" 2750,10175 r270 top (schematic designator TP3)
TP3B "TPAD6R-CIRCLED" "TP06R - Circled" 2750,7125 r270 top (schematic designator TP3)
TP3C "TPAD6R-CIRCLED" "TP06R - Circled" 2750,8075 r270 top (schematic designator TP3)
TP3D "TPAD6R-CIRCLED" "TP06R - Circled" 2750,9225 r270 top (schematic designator TP3)
TP4A "TPAD6R-CIRCLED" "TP06R - Circled" 2250,10175 r270 top (schematic designator TP4)
TP4B "TPAD6R-CIRCLED" "TP06R - Circled" 2250,7125 r270 top (schematic designator TP4)
TP4C "TPAD6R-CIRCLED" "TP06R - Circled" 2250,8075 r270 top (schematic designator TP4)
TP4D "TPAD6R-CIRCLED" "TP06R - Circled" 2250,9225 r270 top (schematic designator TP4)
TP5A "TPAD6R-CIRCLED" "TP06R - Circled" 2700,10225 r270 top (schematic designator TP5)
TP5B "TPAD6R-CIRCLED" "TP06R - Circled" 2700,7175 r270 top (schematic designator TP5)
TP5C "TPAD6R-CIRCLED" "TP06R - Circled" 2700,8125 r270 top (schematic designator TP5)
TP5D "TPAD6R-CIRCLED" "TP06R - Circled" 2700,9275 r270 top (schematic designator TP5)
TP6A "TPAD6R-CIRCLED" "TP06R - Circled" 2200,10225 r270 top (schematic designator TP6)
TP6B "TPAD6R-CIRCLED" "TP06R - Circled" 2200,7175 r270 top (schematic designator TP6)
TP6C "TPAD6R-CIRCLED" "TP06R - Circled" 2200,8125 r270 top (schematic designator TP6)
TP6D "TPAD6R-CIRCLED" "TP06R - Circled" 2200,9275 r270 top (schematic designator TP6)
TP7A "TPAD6R-CIRCLED" "TP06R - Circled" 2600,10225 r270 top (schematic designator TP7)
TP7B "TPAD6R-CIRCLED" "TP06R - Circled" 2600,7175 r270 top (schematic designator TP7)
TP7C "TPAD6R-CIRCLED" "TP06R - Circled" 2600,8125 r270 top (schematic designator TP7)
TP7D "TPAD6R-CIRCLED" "TP06R - Circled" 2600,9275 r270 top (schematic designator TP7)
TP8A "TPAD6R-CIRCLED" "TP06R - Circled" 2100,10225 r270 top (schematic designator TP8)
TP8B "TPAD6R-CIRCLED" "TP06R - Circled" 2100,7175 r270 top (schematic designator TP8)
TP8C "TPAD6R-CIRCLED" "TP06R - Circled" 2100,8125 r270 top (schematic designator TP8)
TP8D "TPAD6R-CIRCLED" "TP06R - Circled" 2100,9275 r270 top (schematic designator TP8)
TP9A "TPAD6R-CIRCLED" "TP06R - Circled" 2650,10175 r270 top (schematic designator TP9)
TP9B "TPAD6R-CIRCLED" "TP06R - Circled" 2650,7125 r270 top (schematic designator TP9)
TP9C "TPAD6R-CIRCLED" "TP06R - Circled" 2650,8075 r270 top (schematic designator TP9)
TP9D "TPAD6R-CIRCLED" "TP06R - Circled" 2650,9225 r270 top (schematic designator TP9)
TP10A "TPAD6R-CIRCLED" "TP06R - Circled" 2150,10175 r270 top (schematic designator TP10)
TP10B "TPAD6R-CIRCLED" "TP06R - Circled" 2150,7125 r270 top (schematic designator TP10)
TP10C "TPAD6R-CIRCLED" "TP06R - Circled" 2150,8075 r270 top (schematic designator TP10)
TP10D "TPAD6R-CIRCLED" "TP06R - Circled" 2150,9225 r270 top (schematic designator TP10)
TP11A "TPAD6R-CIRCLED" "TP06R - Circled" 2600,9725 r270 top (schematic designator TP11)
TP11B "TPAD6R-CIRCLED" "TP06R - Circled" 2600,6675 r270 top (schematic designator TP11)
TP11C "TPAD6R-CIRCLED" "TP06R - Circled" 2600,7625 r270 top (schematic designator TP11)
TP11D "TPAD6R-CIRCLED" "TP06R - Circled" 2600,8775 r270 top (schematic designator TP11)
TP12A "TPAD6R-CIRCLED" "TP06R - Circled" 2100,9725 r270 top (schematic designator TP12)
TP12B "TPAD6R-CIRCLED" "TP06R - Circled" 2100,6675 r270 top (schematic designator TP12)
TP12C "TPAD6R-CIRCLED" "TP06R - Circled" 2100,7625 r270 top (schematic designator TP12)
TP12D "TPAD6R-CIRCLED" "TP06R - Circled" 2100,8775 r270 top (schematic designator TP12)
TP13A "TPAD6R-CIRCLED" "TP06R - Circled" 2650,9775 r270 top (schematic designator TP13)
TP13B "TPAD6R-CIRCLED" "TP06R - Circled" 2650,6725 r270 top (schematic designator TP13)
TP13C "TPAD6R-CIRCLED" "TP06R - Circled" 2650,7675 r270 top (schematic designator TP13)
TP13D "TPAD6R-CIRCLED" "TP06R - Circled" 2650,8825 r270 top (schematic designator TP13)
TP14A "TPAD6R-CIRCLED" "TP06R - Circled" 2150,9775 r270 top (schematic designator TP14)
TP14B "TPAD6R-CIRCLED" "TP06R - Circled" 2150,6725 r270 top (schematic designator TP14)
TP14C "TPAD6R-CIRCLED" "TP06R - Circled" 2150,7675 r270 top (schematic designator TP14)
TP14D "TPAD6R-CIRCLED" "TP06R - Circled" 2150,8825 r270 top (schematic designator TP14)
TP15A "TPAD6R-CIRCLED" "TP06R - Circled" 2750,9775 r270 top (schematic designator TP15)
TP15B "TPAD6R-CIRCLED" "TP06R - Circled" 2750,6725 r270 top (schematic designator TP15)
TP15C "TPAD6R-CIRCLED" "TP06R - Circled" 2750,7675 r270 top (schematic designator TP15)
TP15D "TPAD6R-CIRCLED" "TP06R - Circled" 2750,8825 r270 top (schematic designator TP15)
TP16A "TPAD6R-CIRCLED" "TP06R - Circled" 2250,9775 r270 top (schematic designator TP16)
TP16B "TPAD6R-CIRCLED" "TP06R - Circled" 2250,6725 r270 top (schematic designator TP16)
TP16C "TPAD6R-CIRCLED" "TP06R - Circled" 2250,7675 r270 top (schematic designator TP16)
TP16D "TPAD6R-CIRCLED" "TP06R - Circled" 2250,8825 r270 top (schematic designator TP16)
TP17A "TPAD6R-CIRCLED" "TP06R - Circled" 2700,9725 r270 top (schematic designator TP17)
TP17B "TPAD6R-CIRCLED" "TP06R - Circled" 2700,6675 r270 top (schematic designator TP17)
TP17C "TPAD6R-CIRCLED" "TP06R - Circled" 2700,7625 r270 top (schematic designator TP17)
TP17D "TPAD6R-CIRCLED" "TP06R - Circled" 2700,8775 r270 top (schematic designator TP17)
TP18A "TPAD6R-CIRCLED" "TP06R - Circled" 2200,9725 r270 top (schematic designator TP18)
TP18B "TPAD6R-CIRCLED" "TP06R - Circled" 2200,6675 r270 top (schematic designator TP18)
TP18C "TPAD6R-CIRCLED" "TP06R - Circled" 2200,7625 r270 top (schematic designator TP18)
TP18D "TPAD6R-CIRCLED" "TP06R - Circled" 2200,8775 r270 top (schematic designator TP18)
TP19A "TPAD6R-CIRCLED" "TP06R - Circled" 3600,10175 r270 top (schematic designator TP19)
TP19B "TPAD6R-CIRCLED" "TP06R - Circled" 3600,7125 r270 top (schematic designator TP19)
TP19C "TPAD6R-CIRCLED" "TP06R - Circled" 3600,8075 r270 top (schematic designator TP19)
TP19D "TPAD6R-CIRCLED" "TP06R - Circled" 3600,9225 r270 top (schematic designator TP19)
TP20A "TPAD6R-CIRCLED" "TP06R - Circled" 3150,10175 r270 top (schematic designator TP20)
TP20B "TPAD6R-CIRCLED" "TP06R - Circled" 3150,7125 r270 top (schematic designator TP20)
TP20C "TPAD6R-CIRCLED" "TP06R - Circled" 3150,8075 r270 top (schematic designator TP20)
TP20D "TPAD6R-CIRCLED" "TP06R - Circled" 3150,9225 r270 top (schematic designator TP20)
TP21 "5001" FP-5001-MFG 2375,8750 r0 top
TP22 "5001" FP-5001-MFG 2780,9380 r0 top
TP23 "5001" FP-5001-MFG 2500,9375 r0 top
TP24 "5001" FP-5001-MFG 2500,8625 r0 top
TP25 "5001" FP-5001-MFG 2800,8625 r0 top
U1A "AD8604ARUZ-REEL" ADI-RU-14_M 2675,9975 r270 top (schematic designator U1)
U1B "AD8604ARUZ-REEL" ADI-RU-14_M 2675,6925 r270 top (schematic designator U1)
U1C "AD8604ARUZ-REEL" ADI-RU-14_M 2675,7875 r270 top (schematic designator U1)
U1D "AD8604ARUZ-REEL" ADI-RU-14_M 2675,9025 r270 top (schematic designator U1)
U2A "AD8604ARUZ-REEL" ADI-RU-14_M 2175,9975 r270 top (schematic designator U2)
U2B "AD8604ARUZ-REEL" ADI-RU-14_M 2175,6925 r270 top (schematic designator U2)
U2C "AD8604ARUZ-REEL" ADI-RU-14_M 2175,7875 r270 top (schematic designator U2)
U2D "AD8604ARUZ-REEL" ADI-RU-14_M 2175,9025 r270 top (schematic designator U2)
U3A "MCP1792-5002H/DB" SOT230P700X180-4M 3375,9975 r270 top (schematic designator U3)
U3B "MCP1792-5002H/DB" SOT230P700X180-4M 3375,6925 r270 top (schematic designator U3)
U3C "MCP1792-5002H/DB" SOT230P700X180-4M 3375,7875 r270 top (schematic designator U3)
U3D "MCP1792-5002H/DB" SOT230P700X180-4M 3375,9025 r270 top (schematic designator U3)

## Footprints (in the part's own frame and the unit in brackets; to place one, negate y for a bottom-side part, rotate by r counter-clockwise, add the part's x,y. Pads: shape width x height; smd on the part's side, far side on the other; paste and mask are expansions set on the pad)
61201021721 [mm] "10 pins, right angled, gold plating"
  rrect50% 1.6x1.6 hole 1.1: 1(5.08,8.805)
  round 1.6 hole 1.1: 2(5.08,6.265) 3(2.54,8.805) 4(2.54,6.265) 5(0,8.805) 6(0,6.265) 7(-2.54,8.805) 8(-2.54,6.265) 9(-5.08,8.805) 10(-5.08,6.265)
  silkscreen extent -10.26,-4.5 10.26,4.5, body extent -10.18,-4.42 10.18,9.13, height 9.23
61202621721 [mm] "26 pins, right angled, gold plating"
  rrect50% 1.6x1.6 hole 1.1: 1(15.24,8.805)
  round 1.6 hole 1.1: 2(15.24,6.265) 3(12.7,8.805) 4(12.7,6.265) 5(10.16,8.805) 6(10.16,6.265) 7(7.62,8.805) 8(7.62,6.265) 9(5.08,8.805) 10(5.08,6.265) 11(2.54,8.805) 12(2.54,6.265) 13(0,8.805) 14(0,6.265) 15(-2.54,8.805) 16(-2.54,6.265) 17(-5.08,8.805) 18(-5.08,6.265) 19(-7.62,8.805) 20(-7.62,6.265) 21(-10.16,8.805) 22(-10.16,6.265) 23(-12.7,8.805) 24(-12.7,6.265) 25(-15.24,8.805) 26(-15.24,6.265)
  silkscreen extent -20.42,-4.5 20.42,4.5, body extent -20.34,-4.42 20.34,9.13, height 9.23
61204021721 [mm] "40 pins, right angled, gold plating"
  rrect50% 1.6x1.6 hole 1.1: 1(24.13,8.805)
  round 1.6 hole 1.1: 2(24.13,6.265) 3(21.59,8.805) 4(21.59,6.265) 5(19.05,8.805) 6(19.05,6.265) 7(16.51,8.805) 8(16.51,6.265) 9(13.97,8.805) 10(13.97,6.265) 11(11.43,8.805) 12(11.43,6.265) 13(8.89,8.805) 14(8.89,6.265) 15(6.35,8.805) 16(6.35,6.265) 17(3.81,8.805) 18(3.81,6.265) 19(1.27,8.805) 20(1.27,6.265) 21(-1.27,8.805) 22(-1.27,6.265) 23(-3.81,8.805) 24(-3.81,6.265) 25(-6.35,8.805) 26(-6.35,6.265) 27(-8.89,8.805) 28(-8.89,6.265) 29(-11.43,8.805) 30(-11.43,6.265) 31(-13.97,8.805) 32(-13.97,6.265) 33(-16.51,8.805) 34(-16.51,6.265) 35(-19.05,8.805) 36(-19.05,6.265) 37(-21.59,8.805) 38(-21.59,6.265) 39(-24.13,8.805) 40(-24.13,6.265)
  silkscreen extent -29.31,-4.5 29.31,4.5, body extent -29.23,-4.42 29.23,9.13, height 9.23
ADI-RU-14_M [mm] "SOP, 14-Leads, Body 5x4.4mm, Pitch 0.65mm, IPC Low Density"
  oval 1.85x0.35 smd: 1(-2.925,1.95) 2(-2.925,1.3) 3(-2.925,0.65) 4(-2.925,0) 5(-2.925,-0.65) 6(-2.925,-1.3) 7(-2.925,-1.95) 8(2.925,-1.95) 9(2.925,-1.3) 10(2.925,-0.65) 11(2.925,0) 12(2.925,0.65) 13(2.925,1.3) 14(2.925,1.95)
  silkscreen extent -3.05,-2.55 1.6,2.8, body extent -2.25,-2.55 2.25,2.55, height 1.2
CAPC2013X95X50ML10T25 [mm] "Chip Capacitor, 2-Leads, Body 2.10x1.35mm, IPC Low Density"
  rect 1.45x1.5 smd: 1(-0.925,0) 2(0.925,0)
  body extent -1.05,-0.67 1.05,0.67, height 0.95
CAPC3225X270X30ML30 [mm] "Chip Capacitor, 2-Leads, Body 3.5x2.7mm, IPC Low Density"
  rect 1.15x2.8 smd: 1(-1.725,0) 2(1.725,0)
  silkscreen extent -0.75,-1.3 0.75,1.3, body extent -1.75,-1.35 1.75,1.35, height 2.7
FP-5001-MFG [mm]
  round 1.57 hole 1.016: 1(0,0)
  silkscreen extent -1.34,-1.35 1.34,1.35, body extent -1.45,-1.45 1.45,1.45, height 0.25
FP-5002-MFG [mm]
  round 1.57 hole 1.02 paste-1000 mask+0: 1(0,0)
  silkscreen extent -1.34,-1.35 1.34,1.35, body extent -1.45,-1.45 1.45,1.45, height 0.25
M80-5400442-Footprint-1 [mm]
  rect 1.2x1.2 hole 0.7 paste-1000 mask+0: 1(1,1)
  round 1.2 hole 0.7 paste-1000 mask+0: 2(-1,1) 3(1,-1) 4(-1,-1)
  round 2.25 hole 2.25 unplated paste-1000 mask+0: MT1(-4.5,0) MT2(4.5,0)
  silkscreen extent -7,-7 7,2.63, body extent -7,-6.9 7,2.2, height 6.11
"MH-M3-Footprint-1 - Oversized MARS2" [mil] "Oversized specific for the MARS2 Project."
  round 390 hole 150: 1(0,0)
MPD-BA2032SM_V [mm] "Coin Cell Holder, 2-Leads, Body 28x16mm"
  rect 2.6x3.56 smd: 1(-14.65,0) 2(14.65,0)
  Keep-Out Layer region: -5.5,-3.5 5.5,-3.5 5.5,3.5 -5.5,3.5
  silkscreen extent -17.45,-8 14,8, body extent -14,-8 14,8, height 6.7
RESC1608X55X25ML10T15 [mm] "Chip Resistor, 2-Leads, Body 1.70x0.90mm, IPC Low Density"
  rect 0.8x1 smd: 1(-0.75,0) 2(0.75,0)
  body extent -0.85,-0.45 0.85,0.45, height 0.55
SMTC-ESQ-132-14-X-D [mm] "Elevated Socket, 2x32 Pins, Vertical, 2.54mm Pitch, Female"
  rect 1.55x1.55 hole 1.02: 1(0,0)
  round 1.55 hole 1.02: 2(0,-2.54) 3(2.54,0) 4(2.54,-2.54) 5(5.08,0) 6(5.08,-2.54) 7(7.62,0) 8(7.62,-2.54) 9(10.16,0) 10(10.16,-2.54) 11(12.7,0) 12(12.7,-2.54) 13(15.24,0) 14(15.24,-2.54) 15(17.78,0) 16(17.78,-2.54) 17(20.32,0) 18(20.32,-2.54) 19(22.86,0) 20(22.86,-2.54) 21(25.4,0) 22(25.4,-2.54) 23(27.94,0) 24(27.94,-2.54) 25(30.48,0) 26(30.48,-2.54) 27(33.02,0) 28(33.02,-2.54) 29(35.56,0) 30(35.56,-2.54) 31(38.1,0) 32(38.1,-2.54) 33(40.64,0) 34(40.64,-2.54) 35(43.18,0) 36(43.18,-2.54) 37(45.72,0) 38(45.72,-2.54) 39(48.26,0) 40(48.26,-2.54) 41(50.8,0) 42(50.8,-2.54) 43(53.34,0) 44(53.34,-2.54) 45(55.88,0) 46(55.88,-2.54) 47(58.42,0) 48(58.42,-2.54) 49(60.96,0) 50(60.96,-2.54) 51(63.5,0) 52(63.5,-2.54) 53(66.04,0) 54(66.04,-2.54) 55(68.58,0) 56(68.58,-2.54) 57(71.12,0) 58(71.12,-2.54) 59(73.66,0) 60(73.66,-2.54) 61(76.2,0) 62(76.2,-2.54) 63(78.74,0) 64(78.74,-2.54)
  silkscreen extent -1.53,-3.74 80.27,1.2, body extent -1.52,-3.81 80.26,1.27, height 11.05
SOT230P700X180-4M [mm] "SOT223, 4-Leads, Body 6.50x7.00mm (avg), Pitch 2.30mm, IPC Low Density"
  rect 2.35x1 smd: 1(-3.025,2.3) 2(-3.025,0) 3(-3.025,-2.3)
  rect 2.35x3.25 smd: 4(3.025,0)
  silkscreen extent -3.15,-3.35 1.55,3.48, body extent -3.5,-3.35 3.5,3.35, height 1.8
TestPoint-5005-Footprint-1 [mil]
  round 103 hole 63: 1(0,0)
  silkscreen extent -72,-72 72,72, body extent -63,-61 62,64, height 215
"TP06R - Circled" [mm] "Testpoint, round, d=0.6mm"
  round 0.6 smd paste-1: 1(0,0)
  silkscreen extent -0.51,-0.51 0.51,0.51

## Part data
BT1: library part CMP-002-00003-2, "Coin Cell Holder, 1 Cell, -40 to 225 degC, 2-Pin SMD, RoHS, Tray", Manufacturer="Memory Protection Devices", Max Operating Temperature=225°C, Min Operating Temperature=-40°C, Package Description="2-Pin Surface Mount Device, Body 28 x 16 mm", Package Quantity=100
C1A C1B C1C C1D C2A C2B C2C C2D: library part CMP-001-00167-10, "Chip Capacitor, 2.2uF, 10%, 50 V, X7R 0805 (2012 Metric)", Capacitance=2.2uF, Capacitor Type=Ceramic, Case/Package=0805, Dielectric=X7R, Max Operating Temperature=125°C, Min Operating Temperature=-55°C, Tolerance=10%, Voltage Rating=50V
C3A C3B C3C C3D C4A C4B C4C C4D: library part CMP-001-00181-9, "Chip Capacitor, 1uF, 10%, 50 V, X7R 1210 (3225 Metric)", Capacitance=1uF, Capacitor Type=Ceramic, Case/Package=1210, Dielectric=X7R, Max Operating Temperature=125°C, Min Operating Temperature=-55°C, Tolerance=10%, Voltage Rating=50V
J1 J2: library part CMP-002-00093-2, "Conn Elevated Socket SKT 64 POS 2.54mm Solder ST Top Entry Thru-Hole Tube", Color=Black, Contact Resistance=10mR, Current Rating=6.9A, Max Operating Temperature=125°C, Max Voltage Rating (AC)=550V, Min Operating Temperature=-55°C, Package Quantity=1
J3 J5: library part CMP-002-00095-3, "HARWIN - M80-5400442 - Wire-To-Board Connector, 2 mm, 4 Contacts, Header, Datamate J-Tek M80 Series, Through Hole, 2 Rows", Color=Black, Contact Resistance=25mR, Current Rating=2.2A, Insulation Resistance=100MR, Manufacturer=Harwin, Max Operating Temperature=125°C, Maximum Voltage=800V, Min Operating Temperature=-55°C
J6 J7 J8 J9 J10 J13 J15 J17 J19: library part CMP-002-00083-3, "TEST POINT PC MINI .040D WHITE", Color=White
J11 J12 J14 J16 J18 J20 TP21 TP22 TP23 TP24 TP25: library part CMP-001-0002-3, "TEST POINT PC MINI .040D BLACK", Color=Black
MH1 MH2 MH3 MH4 MH5 MH6 MH7 MH8 MH9 MH10 MH11: library part CMP-00028-00015-1, "MARS2 Project 6-32 Mounting Hole Plated ."
P1A P1B: library part CMP-002-00158-1, "WR-BHD Angled Male, Box Header, Through Hole, 2 Rows, 40 Contacts, 2.54mm Pitch", Current Rating=3A, Max Operating Temperature=125°C, Min Operating Temperature=-55°C, Voltage Rating=250V
P2A P2B: library part CMP-002-00157-1, "WR-BHD Angled Male, Box Header, Through Hole, 2 Rows, 26 Contacts, 2.54mm Pitch", Current Rating=3A, Max Operating Temperature=125°C, Min Operating Temperature=-40°C, Voltage Rating=250V
P3A P3B: library part CMP-002-00155-1, "WR-BHD Angled Male, Box Header, Through Hole, 2 Rows, 10 Contacts, 2.54mm Pitch", Current Rating=3A, Max Operating Temperature=125°C, Min Operating Temperature=-40°C, Voltage Rating=250V
R1 R2 R3 R4 R5 R6 R7 R8 R9 R10 R11 R12 R13 R14 R15 R16 R17 R18 R19 R20 R21 R22 R23 R24 R25 R26 R27 R28 R29: library part CMP-009-00017-7, "Chip Resistor, 10 KOhm, +/- 1%, 01 W, -55 to 155 degC, 0603 (1608 Metric)", Case/Package=0603, Max Operating Temperature=155°C, Min Operating Temperature=-55°C, Power=100mW, Tolerance=1%, Voltage Rating=50V
TP1 TP2: library part CMP-001-0000-5, "PC TEST POINT COMPACT RED", Color=Red
TP3A TP3B TP3C TP3D TP4A TP4B TP4C TP4D TP5A TP5B TP5C TP5D TP6A TP6B TP6C TP6D TP7A TP7B TP7C TP7D TP8A TP8B TP8C TP8D TP9A TP9B TP9C TP9D TP10A TP10B TP10C TP10D TP11A TP11B TP11C TP11D TP12A TP12B TP12C TP12D TP13A TP13B TP13C TP13D TP14A TP14B TP14C TP14D TP15A TP15B TP15C TP15D TP16A TP16B TP16C TP16D TP17A TP17B TP17C TP17D TP18A TP18B TP18C TP18D TP19A TP19B TP19C TP19D TP20A TP20B TP20C TP20D: library part CMP-00028-00014-1, "0.6mm round with a silkscreen circle."
U1A U1B U1C U1D U2A U2B U2C U2D: library part CMP-014-00034-2, "IC OPAMP GP 8.4MHZ RRO 14TSSOP", Case/Package=TSSOP, Input Bias Current=0.2pA, Input Offset Voltage (Vos)=600uV, Input Voltage Noise Density="33nV/sqrt Hz", Max Operating Temperature=125°C, Max Supply Voltage=5.5V, Min Operating Temperature=-40°C, Min Supply Voltage=2.7V, Operating Supply Current=4.8mA, Output Current per Channel=50mA, Power Supply Rejection Ratio (PSRR)=75dB, Quiescent Current=1.2mA, Voltage Gain=98.06dB
U3A U3B U3C U3D: library part CMP-019-00076-2, "High input voltage regulator 5.0 V 3Ld SOT-223 3 SOT-223 TUBE RoHS Compliant: Yes", Case/Package=SOT-223-3, Dropout Voltage=1.2V, Max Input Voltage=55V, Max Operating Temperature=150C, Max Ouput Current=100mA, Min Input Voltage=6.2V, Min Operating Temperature=-40C

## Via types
v1: diameter 35, hole 15, Top Layer to Bottom Layer, 157 vias
v2: diameter 25, hole 15, Top Layer to Bottom Layer, 17 vias

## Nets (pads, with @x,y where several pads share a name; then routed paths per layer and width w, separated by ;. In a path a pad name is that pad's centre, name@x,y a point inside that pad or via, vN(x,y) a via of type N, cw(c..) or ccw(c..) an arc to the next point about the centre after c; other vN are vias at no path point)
24V_UNSWCH_BUS_CURRENT: J2.18 TP6D.1 U2D.3 | length 16550.5
  Top Layer w10: v1(2193.23,9495.16) 2197.39,9490.99 2197.39,9277.61 TP6D.1@2200,9275 ; TP6D.1@2200.3,9274.7 2200.3,9140.45 U2D.3@2200.59,9140.16
  Int2 (Sign) w10: v1(2193.23,9495.16) 2924.84,9495.16 3020,9400 v1(6592.5,9400)
  Int3 (Sign) w10: J2.18@3200,400 3200,575 3432.5,807.5 4057.28,1432.28 5481.98,1432.28 5830.56,1432.28 5873.85,1432.28 5896.98,1432.28 6350,1885.29 6350,4449.79 6070,4729.79 6040,4759.79 6040,7688.58 6360,8008.58 6360,8493.14 6595,8728.14 6595,8893.43 6577.5,8910.93 6577.5,9139.13 6592.5,9154.13 v1(6592.5,9400)
24V_UNSWCH_BUS_CURRENT_BUF: P1B.15 TP4D.1 U2D.1 U2D.2 | length 3319.8
  Top Layer w10: U2D.2@2226.18,9140.16 U2D.1@2251.77,9140.16 2251.05,9140.88 2251.05,9223.95 TP4D.1@2250,9225 ; TP4D.1@2250.36,9225.36 v1(2250.36,9375.36)
  Int2 (Sign) w10: v1(2250.36,9375.36) 2355.72,9270 v1(4675,9270)
  Int3 (Sign) w10: v1(4675,9270) 4675,9630.82 4700,9655.82 P1B.15@4700,9850
BAYCAT_3V3: J1.18 J5.3 | length 3375.4
  Int3 (Sign) w10: J5.3@440,10900 500,10840 2740,10840 3150,11250 3150,11650 J1.18@3200,11700
DIO_SPARE_0: J1.2 J6.1 | length 2302.4
  Int3 (Sign) w10: J1.2@4000,11700 4365,11335 5265,11335 5630,11700 J6.1@6000,11700
DIO_SPARE_1: J1.4 J7.1 | length 2735
  Int3 (Sign) w10: J1.4@3900,11700 3909.76,11709.76 3909.76,11744.76 3945,11780 4035,11780 4410,11405 5235,11405 5595,11765 6185,11765 J7.1@6250,11700
DIO_SPARE_2: J1.6 J8.1 | length 6255.6
  Int2 (Sign) w10: J1.6@3800,11700 3850,11650 3850,11537.25 4112.25,11275 6120,11275 6475,11630 J8.1@6475,11700
  Int3 (Sign) w10: J1.6@3800,11700 3800,11755 3880,11835 4080,11835 4435,11480 5135,11480 5500,11845 6330,11845 J8.1@6475,11700
DIO_SPARE_3: J1.8 J9.1 | length 3475.7
  Int2 (Sign) w10: J1.8@3700,11700 3713.81,11700 3750,11663.81 3750,11535 4080,11205 5512.5,11205 5547.5,11240 6450,11240 6500,11290 J9.1@6860,11290
DIO_SPARE_4: J1.10 J10.1 | length 3627.3
  Int2 (Sign) w10: J1.10@3600,11700 3650,11650 3650,11525 4030,11145 6305,11145 6355,11195 6755,11195 J10.1@6860,11090
DIO_SPARE_5: J1.12 J13.1 | length 3810.2
  Int2 (Sign) w10: J1.12@3500,11700 3554.49,11645.51 3554.49,11520.51 3980,11095 6325,11095 6375,11145 6605,11145 J13.1@6860,10890
DIO_SPARE_6: J1.14 J15.1 | length 3948.7
  Int2 (Sign) w10: J1.14@3400,11700 3450,11650 3450,11535 3955,11030 6525,11030 6860,10695 J15.1@6860,10690
DIO_SPARE_7: J1.16 J17.1 | length 4204.7
  Int2 (Sign) w10: J1.16@3300,11700 3350,11650 3350,11525 3920,10955 6515,10955 6860,10610 J17.1@6860,10490
FAULT_MUX_A: J2.58 P2B.14 | length 5578.6
  Int2 (Sign) w10: J2.58@1200,400 1200,710 2440,1950 v1(2440,2810)
  Int3 (Sign) w10: v1(2440,2810) 2485,2855 3410,2855 4295,2855 4600,2550 P2B.14@4600,2200
FAULT_MUX_B: J2.60 P2B.13 | length 4966.3
  Int2 (Sign) w10: J2.60@1100,400 1100,938.89 1516.6,1355.49 1733.47,1355.49 2265,1887.03 v1(2265,2140)
  Int3 (Sign) w10: v1(2265,2140) 2270.96,2140 2290.96,2160 3030,2160 3390,1800 4300,1800 P2B.13@4600,2100
FAULT_MUX_C: J2.62 P2B.16 | length 6117.3
  Int2 (Sign) w10: J2.62@1000,400 1000,881.32 1504.18,1385.49 1721.04,1385.49 2160,1824.46 v1(2160,2850)
  Int3 (Sign) w10: v1(2160,2850) 2215,2905 3410,2905 4345,2905 4700,2550 P2B.16@4700,2200
FAULT_SENSE_HPB: J2.55 P1B.31 | length 14479
  Int2 (Sign) w10: v1(700,1120) 700,1120.96 672.5,1148.46 672.5,4296.54 727.5,4351.54 727.5,8338.1 924.4,8535 3565,8535 4105,9075 v1(5500,9075)
  Int3 (Sign) w10: v1(700,1120) 879.74,1120 891.36,1131.62 1193.38,1131.62 1250,1075 1250,350 J2.55@1300,300 ; v1(5500,9075) P1B.31@5500,9850
FAULT_SENSE_IPB1: J2.51 P1B.32 | length 14469.1
  Int2 (Sign) w10: v1(800,1350) 842.5,1392.5 842.5,2951.11 830,2963.61 830,8340.6 994.4,8505 3590,8505 4105,9020 v1(5400,9020)
  Int3 (Sign) w10: v1(800,1350) 1300,1350 1450,1200 1450,350 J2.51@1500,300 ; v1(5400,9020) 5400,9720 5455,9775 5455,9905 P1B.32@5500,9950
FAULT_SENSE_IPB2: J2.53 P1B.33 | length 14280.9
  Int2 (Sign) w10: v1(890,1190) 890,1560 907.5,1577.5 907.5,2939.52 937.5,2969.52 937.5,4331.54 957.5,4351.54 957.5,8372.5 1060,8475 3602.43,8475 3947.43,8820 4069.04,8820 4085.29,8836.25 5461.25,8836.25 v1(5600,8975)
  Int3 (Sign) w10: v1(890,1190) 1235,1190 1325,1100 1325,439.36 1345.51,418.85 1345.51,354.49 J2.53@1400,300 ; v1(5600,8975) P1B.33@5600,9850
GF_AMP_TEMP_F: J2.59 TP10C.1 U2C.5 | length 9184.7
  Top Layer w10: U2C.5@2149.41,7990.16 2149.7,7990.45 2149.7,8074.7 TP10C.1@2150,8075 v1(2150,8285)
  Int2 (Sign) w10: v1(975,1050) 1018.38,1093.38 1018.38,1112.58 1087.5,1181.7 1087.5,2732.02 1110,2754.52 1110,4324.04 1137.5,4351.54 1137.5,7897.5 1525,8285 v1(2150,8285)
  Int3 (Sign) w10: v1(975,1050) 1050,975 1050,350 J2.59@1100,300
GF_AMP_TEMP_F_BUF: P1A.22 TP8C.1 U2C.6 U2C.7 | length 3719
  Top Layer w10: v1(2100,8225) TP8C.1@2100,8125 2098.95,8123.95 2098.95,7990.88 U2C.7@2098.23,7990.16 U2C.6@2123.82,7990.16
  Int2 (Sign) w10: v1(2100,8225) 2250,8075 v1(4950,8075)
  Int3 (Sign) w10: v1(4950,8075) 4954.78,8079.78 4954.78,8092.14 4956,8093.36 4956,8556 P1A.22@5000,8600
GF_ANNODE_SEL_EN: J2.9 P2A.6 | length 4094.9
  Int2 (Sign) w10: J2.9@3600,300 3554.49,345.51 3554.49,767.06 3605,817.57 3605,831.72 3680,906.72 3680,3243.28 3600,3323.28 v1(3600,3635)
  Int3 (Sign) w10: v1(3600,3635) 3625,3660 4090,3660 P2A.6@4200,3550
GF_CHASSIS_SEL_EN: J2.11 P2A.5 | length 3881.8
  Int2 (Sign) w10: J2.11@3500,300 3450,350 3450,705 3660,915 3660,3235 v1(3555,3340)
  Int3 (Sign) w10: v1(3555,3340) 4090,3340 P2A.5@4200,3450
GF_SIG: J2.47 P1A.11 | length 12257.9
  Int2 (Sign) w10: v1(950,1450) 992.5,1492.5 992.5,2673.46 997.5,2678.46 997.5,2899.52 1020,2922.02 1020,4324.04 1047.5,4351.54 1047.5,8342.1 1100.4,8395 4480,8395 4505,8420 P1A.11@4505,8495 P1A.11@4500,8500
  Int3 (Sign) w10: v1(950,1450) 1450,1450 1650,1250 1650,350 J2.47@1700,300
GF_SOURCE_SEL_A: J2.1 P2A.2 | length 3624.8
  Int2 (Sign) w10: v1(3740,3555) 3740,3549.04 3760,3529.04 3760,808.98 3950,618.98 3950,350 J2.1@4000,300
  Int3 (Sign) w10: v1(3740,3555) 3742.5,3552.5 3997.5,3552.5 P2A.2@4000,3550
GF_SOURCE_SEL_B: J2.3 P2A.1 | length 3519.7
  Int2 (Sign) w10: v1(3709.27,3450) 3740,3419.27 3740,786.56 3850,676.56 3850,350 J2.3@3900,300
  Int3 (Sign) w10: v1(3709.27,3450) P2A.1@4000,3450
GF_SOURCE_SEL_C: J2.5 P2A.4 | length 3808.2
  Int2 (Sign) w10: v1(3675,3590) 3675,3304.85 3720,3259.85 3720,764.13 3750,734.13 3750,350 J2.5@3800,300
  Int3 (Sign) w10: v1(3675,3590) 3705,3620 4030,3620 P2A.4@4100,3550
GF_SOURCE_SEL_ENn: J2.7 P2A.3 | length 3647.4
  Int2 (Sign) w10: v1(3635,3395) 3635,3316.57 3700,3251.57 3700,898.43 3654.49,852.92 3654.49,345.51 J2.7@3700,300
  Int3 (Sign) w10: v1(3635,3395) 4045,3395 P2A.3@4100,3450
GND: C1A.1 C1B.1 C1C.1 C1D.1 C2A.1 C2B.1 C2C.1 C2D.1 C3A.2 C3B.2 C3C.2 C3D.2 C4A.2 C4B.2 C4C.2 C4D.2 J1.20 J1.24 J1.28 J1.32 J1.54 J1.55 J1.57 J1.59 J1.61 J1.63 J2.4 J2.8 J2.12 J2.13 J2.16 J2.17 J2.20 J2.21 J2.24 J2.25 J2.28 J2.29 J2.32 J2.33 J2.37 J2.40 J2.41 J2.44 J2.45 J2.48 J2.49 J2.52 J2.56 J5.4 J11.1 J12.1 J14.1 J16.1 J18.1 J20.1 P1A.9 P1A.10 P1A.19 P1A.20 P1A.29 P1A.30 P1A.39 P1A.40 P1B.9 P1B.10 P1B.19 P1B.20 P1B.29 P1B.30 P1B.39 P1B.40 P2A.17 P2A.18 P2A.19 P2A.20 P2A.21 P2A.22 P2A.23 P2A.24 P2A.25 P2A.26 P2B.17 P2B.18 P2B.19 P2B.20 P2B.21 P2B.22 P2B.23 P2B.24 P2B.25 P2B.26 P3A.1 P3A.3 P3A.5 P3A.7 P3A.9 P3A.10 P3B.1 P3B.3 P3B.5 P3B.7 P3B.9 P3B.10 R1.1 R2.2 R3.2 R4.2 R5.2 R6.2 R7.2 R8.2 R9.2 R10.2 R11.2 R12.2 R13.1 R14.1 R15.1 R16.1 R17.1 R18.1 R19.1 R20.1 R21.1 R22.1 R23.1 R24.2 R25.1 R26.1 R27.1 R28.1 R29.1 U1A.11 U1B.11 U1C.11 U1D.11 U2A.11 U2B.11 U2C.11 U2D.11 U3A.2 U3A.4 U3B.2 U3B.4 U3C.2 U3C.4 U3D.2 U3D.4
  other v2: 3600,570 3800,580 3495.55,629.45 3395.55,729.45 3250,775 1200,830 3225,1150 3100,1225 1510,1310 3100,1550 727.5,2775 1137.5,2775 970,2780 637.5,2975 857.5,2975 1047.5,2975 1227.5,2975
HCB_MEDIA_EN: J1.30 P2B.11 | length 11512.8
  Int3 (Sign) w10: v1(2860,2200) 3030,2200 3400,1830 4230,1830 P2B.11@4500,2100
  Bottom Layer w10: J1.30@2600,11700 2650,11650 2650,11470 2860,11260 v1(2860,2200)
HPB_5V_CURRENT: J2.34 TP9A.1 U1A.5 | length 16924.8
  Top Layer w10: U1A.5@2649.41,10090.16 2649.7,10090.45 2649.7,10174.7 TP9A.1@2650,10175 ; v1(2650,10402.5) 2650,10176.77 TP9A.1@2650.89,10175.89
  Int2 (Sign) w10: v1(2650,10402.5) 2695.76,10402.5 2728.26,10435 2775.15,10435 3190.15,10850 4223.23,10850 4443.23,10630 6135,10630 v1(6297.5,10467.5)
  Int3 (Sign) w10: J2.34@2400,400 2400,485 3077.5,1162.5 3135.07,1162.5 3554.85,1582.28 5030.42,1582.28 5495,2046.86 5495,4160.15 5897.5,4562.65 5897.5,6688.31 5882.5,6703.31 5882.5,7795.93 6240,8153.43 6240,8542.84 6332.5,8635.34 6332.5,9314.05 6297.5,9349.05 v1(6297.5,10467.5)
HPB_5V_CURRENT_BUF: P1B.12 TP7A.1 U1A.6 U1A.7 | length 2890.8
  Top Layer w10: v1(2600,10382.5) TP7A.1@2600,10225 2600,10122.48 2598.23,10120.71 U1A.7@2598.23,10090.16 U1A.6@2623.82,10090.16
  Int2 (Sign) w10: v1(2600,10382.5) 2604.78,10377.72 2628.82,10377.72 2636.54,10370 2691.55,10370 2736.55,10415 2797.57,10415 2822.57,10440 3710,10440 3825,10555 v1(4475,10555)
  Int3 (Sign) w10: v1(4475,10555) 4475,10047.57 4500,10022.57 P1B.12@4500,9950
HPB_5V_VOLTAGE: J2.30 TP17A.1 U1A.12 | length 16499.6
  Top Layer w10: TP17A.1@2700,9725 TP17A.1@2700.15,9725.15 ; v1(2700.3,9632.5) 2700.15,9632.65 TP17A.1@2700.15,9725.15 ; U1A.12@2700.59,9859.84 2700.3,9859.55 2700.3,9725.3 TP17A.1@2700.15,9725.15
  Int2 (Sign) w10: v1(2700.3,9632.5) 2702.8,9630 2810,9630 2945,9765 4740,9765 4760,9745 6275,9745 v1(6350,9820)
  Int3 (Sign) w10: J2.30@2600,400 2600,485 3172.5,1057.5 3647.28,1532.28 5855.56,1532.28 6250,1926.72 6250,4408.37 5940,4718.37 5940,7730 6260,8050 6260,8534.56 6352.5,8627.06 6352.5,9817.5 v1(6350,9820)
HPB_5V_VOLTAGE_BUF: P1B.14 TP15A.1 U1A.13 U1A.14 | length 2434.4
  Top Layer w10: U1A.13@2726.18,9859.84 U1A.14@2751.77,9859.84 2751.05,9859.12 2751.05,9776.05 TP15A.1@2750,9775 2752.5,9772.5 2752.5,9665 v1(2755,9662.5)
  Int2 (Sign) w10: v1(2755,9662.5) 3212.5,10120 v1(4595,10120)
  Int3 (Sign) w10: v1(4595,10120) 4595,10113.24 4605,10103.24 P1B.14@4605,9945
HPB_24V_CURRENT: J2.26 TP5A.1 U1A.3 | length 17566.3
  Top Layer w10: v1(2692.84,10445.54) 2697.39,10440.99 2697.39,10227.61 TP5A.1@2700,10225 ; TP5A.1@2700.3,10224.7 2700.3,10090.45 U1A.3@2700.59,10090.16
  Int2 (Sign) w10: v1(2692.84,10445.54) 2693.61,10445.54 3118.07,10870 4231.51,10870 4431.51,10670 4445.65,10670 4465.65,10650 6335,10650 v1(6485,10500)
  Int3 (Sign) w10: J2.26@2800,400 2800,475 3282.5,957.5 3817.28,1492.28 5457.13,1492.28 5872.13,1492.28 6290,1910.15 6290,4424.94 6010,4704.94 5980,4734.94 5980,7713.43 6300,8033.43 6300,8517.99 6432.5,8650.49 6432.5,9584.89 6485,9637.39 v1(6485,10500)
HPB_24V_CURRENT_BUF: P1B.11 TP3A.1 U1A.1 U1A.2 | length 2643.9
  Top Layer w10: U1A.2@2726.18,10090.16 U1A.1@2751.77,10090.16 2751.77,10120.71 2750,10122.48 TP3A.1@2750,10175 2750.01,10320 v1(2750.01,10382.5)
  Int2 (Sign) w10: v1(2750.01,10382.5) 2754.79,10377.72 2777.32,10377.72 2785.04,10370 2795.04,10370 2845.04,10420 3725,10420 3740,10435 v1(4425,10435)
  Int3 (Sign) w10: v1(4425,10435) 4422.5,10432.5 4422.5,10072.5 4452,10043 4452,9898 P1B.11@4500,9850
HPB_24V_VOLTAGE: J2.22 TP13A.1 U1A.10 | length 16483.4
  Top Layer w10: U1A.10@2649.41,9859.84 2649.7,9859.55 2649.7,9775.3 TP13A.1@2650,9775 2650.1,9774.9 2650.1,9602.6 v1(2650.2,9602.5)
  Int2 (Sign) w10: v1(2650.2,9602.5) 2652.7,9600 2890,9600 3015,9725 6482.5,9725 v1(6542.5,9785)
  Int3 (Sign) w10: J2.22@3000,400 3000,475 3382.5,857.5 3977.28,1452.28 5822.28,1452.28 5865.56,1452.28 5888.7,1452.28 6330,1893.58 6330,4441.51 6050,4721.51 6020,4751.51 6020,7696.86 6340,8016.86 6340,8501.42 6575,8736.42 6575,8885.14 6542.5,8917.64 v1(6542.5,9785)
HPB_24V_VOLTAGE_BUF: P1B.13 TP11A.1 U1A.8 U1A.9 | length 2721.8
  Top Layer w10: v1(2605,9655) 2602.5,9657.5 2602.5,9722.5 TP11A.1@2600,9725 2600,9827.52 2598.23,9829.29 U1A.8@2598.23,9859.84 U1A.9@2623.82,9859.84
  Int2 (Sign) w10: v1(2605,9655) 3125,10175 v1(4520,10175)
  Int3 (Sign) w10: v1(4520,10175) 4520,10045 4555,10010 4555,9895 P1B.13@4600,9850
HPB_CISCO1_CURRENT: J2.2 TP6A.1 U2A.3 | length 17221.4
  Top Layer w10: v1(2192.93,10444.86) 2197.39,10440.4 2197.39,10229.08 TP6A.1@2200.74,10225.74 ; TP6A.1@2200,10225 2200.3,10224.7 2200.3,10090.45 U2A.3@2200.59,10090.16
  Int2 (Sign) w10: v1(2192.93,10444.86) 2422.28,10444.86 2887.42,10910 4248.08,10910 4448.08,10710 6620,10710 v1(6730,10600)
  Int3 (Sign) w10: J2.2@4000,400 4000,475 4715,1190 5835,1190 6480,1835 6480,8471.72 6745.48,8737.2 6745.48,10550.48 6722.6,10573.36 6722.6,10581.64 6725.22,10584.25 6725.22,10595.22 v1(6730,10600)
HPB_CISCO1_CURRENT_BUF: P1B.5 TP4A.1 U2A.1 U2A.2 | length 2771.8
  Top Layer w10: U2A.2@2226.18,10090.16 U2A.1@2251.77,10090.16 2251.05,10090.88 2251.05,10173.95 TP4A.1@2250,10175 v1(2250,10362.5)
  Int2 (Sign) w10: v1(2250,10362.5) 2574.04,10362.5 2586.54,10350 3294.59,10350 3344.59,10400 v1(4100,10400)
  Int3 (Sign) w10: v1(4100,10400) 4100,10070 4154,10016 4154,9886 4190,9850 P1B.5@4200,9850
HPB_CISCO1_EN: J1.49 P2B.10 | length 13517.4
  Top Layer w10: v1(610,2730) 610,2845.19 615,2850.19 615,2958.61 605,2968.61 605,10530 1590.32,11515.32 1590.32,11590.32 J1.49@1600,11600
  Int3 (Sign) w10: v1(610,2730) 1168.03,2730 1185.53,2747.5 4202.5,2747.5 4400,2550 P2B.10@4400,2200
HPB_CISCO2_CURRENT: J2.6 TP10A.1 U2A.5 | length 17317.2
  Top Layer w10: U2A.5@2149.41,10090.16 2149.7,10090.45 2149.7,10174.7 TP10A.1@2150,10175 ; v1(2149.7,10384.7) 2149.85,10384.56 2149.85,10176.33 TP10A.1@2150.59,10175.59
  Int2 (Sign) w10: v1(2149.7,10384.7) 2177.36,10412.36 2448.24,10412.36 2925.88,10890 4239.79,10890 4439.79,10690 6535.48,10690 6683.68,10541.8 6708.2,10541.8 v1(6712.98,10537.02)
  Int3 (Sign) w10: J2.6@3800,400 3800,480 4540,1220 5836.72,1220 6450,1833.28 6450,8470 6713.76,8733.76 6713.76,9795.46 6712.98,9796.24 v1(6712.98,10537.02)
HPB_CISCO2_CURRENT_BUF: P1B.6 TP8A.1 U2A.6 U2A.7 | length 2769.9
  Top Layer w10: v1(2100,10342.5) TP8A.1@2100,10225 2098.95,10223.95 2098.95,10090.88 U2A.7@2098.23,10090.16 U2A.6@2123.82,10090.16
  Int2 (Sign) w10: v1(2100,10342.5) 2224.04,10342.5 2236.54,10330 3340,10330 3360,10350 v1(4155,10350)
  Int3 (Sign) w10: v1(4155,10350) 4155,10070 4205,10020 4205,9955 P1B.6@4200,9950
HPB_CISCO2_EN: J1.51 P2B.9 | length 13852.2
  Top Layer w10: v1(545,2280) 545,4435.07 550,4440.07 550,6588.38 540,6598.38 540,10565 1500,11525 J1.51@1500,11600
  Int3 (Sign) w10: v1(545,2280) 684.04,2280 714.04,2250 3030,2250 3420,1860 4160,1860 P2B.9@4400,2100
HPB_ISO24V_CURRENT: J2.14 TP18A.1 U2A.12 | length 16442
  Top Layer w10: v1(2200,9610) TP18A.1@2200,9725 2200.3,9725.3 2200.3,9859.55 U2A.12@2200.59,9859.84
  Int2 (Sign) w10: v1(2200,9610) 2570,9610 2590,9590 2592.43,9590 2612.43,9570 2910,9570 3045,9705 6595,9705 v1(6630,9740)
  Int3 (Sign) w10: J2.14@3400,400 3400,480 3580,660 4200,1280 5840.15,1280 6410,1849.85 6410,8486.57 6673.76,8750.33 6673.76,9259.48 6630,9303.24 v1(6630,9740)
HPB_ISO24V_CURRENT_BUF: P1B.8 TP16A.1 U2A.13 U2A.14 | length 2772.3
  Top Layer w10: U2A.13@2226.18,9859.84 U2A.14@2251.77,9859.84 2251.77,9829.29 2250,9827.52 TP16A.1@2250,9775 2252.5,9772.5 2252.5,9657.5 v1(2255,9655)
  Int2 (Sign) w10: v1(2255,9655) 2815,10215 v1(4295,10215)
  Int3 (Sign) w10: v1(4295,10215) 4297.5,10212.5 4297.5,9952.5 P1B.8@4300,9950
